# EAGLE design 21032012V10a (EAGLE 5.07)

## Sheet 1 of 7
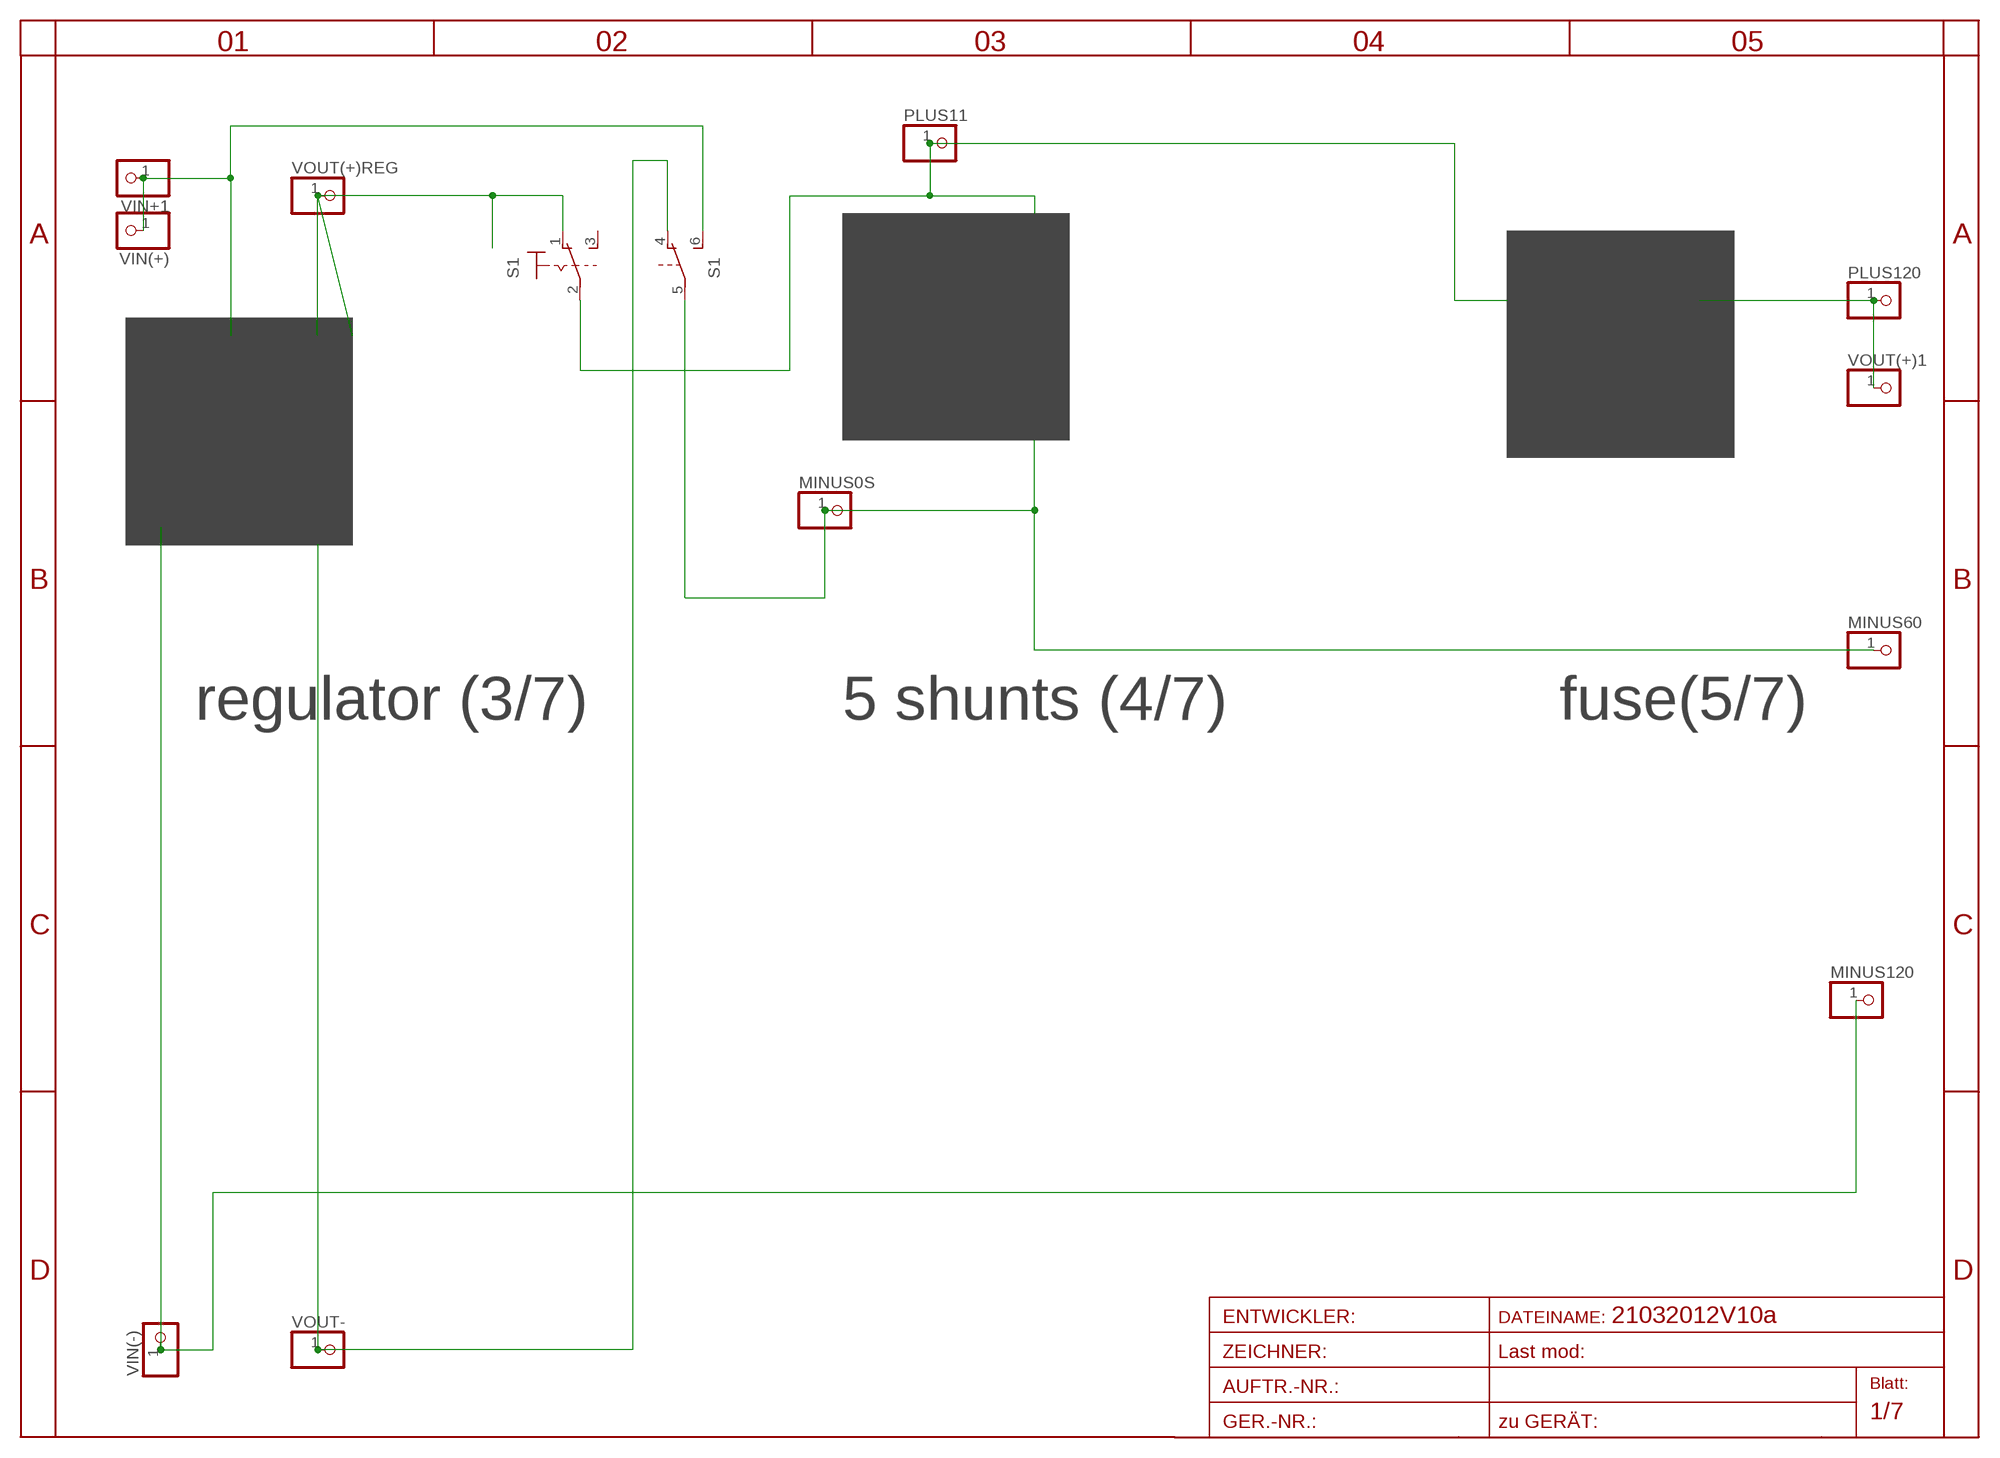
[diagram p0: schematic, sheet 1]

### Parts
MINUS0S  PINHD-1X14.5MM  [1X4MM5]
MINUS60  PINHD-1X14.5MM  [1X4MM5]
MINUS120  PINHD-1X14.5MM  [1X4MM5]
PLUS11  PINHD-1X14.5MM  [1X4MM5]
PLUS120  PINHD-1X14.5MM  [1X4MM5]
S1  320-938320NEW  [320NEW]
VIN(+)  PINHD-1X11MM6  [1X1MM8]
VIN(-)  PINHD-1X1  [1X01]
VIN+1  PINHD-1X1  [1X01]
VOUT(+)1  PINHD-1X11X0.4  [1X01]
VOUT(+)REG  PINHD-1X11X0.4  [1X01]
VOUT-  PINHD-1X11X0.4  [1X01]

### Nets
BATT-: MINUS0S.1 MINUS60.1 S1.5(B:P) ; also sheet 4,5,6,7
IN-: MINUS120.1 VIN(-).1 ; also sheet 3
PLUS11: PLUS11.1 S1.2(1:P) ; also sheet 4
V+OUT: PLUS120.1 VOUT(+)1.1 ; also sheet 5
V-: S1.4(B:O) VOUT-.1 ; also sheet 3
VIN+: S1.6(B:S) VIN(+).1 VIN+1.1 ; also sheet 3
VOUT+REG: S1.1(1:O) VOUT(+)REG.1 ; also sheet 3
Unconnected: S1.3(1:S)

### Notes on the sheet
- regulator (3/7) | 5 shunts (4/7) | fuse(5/7)

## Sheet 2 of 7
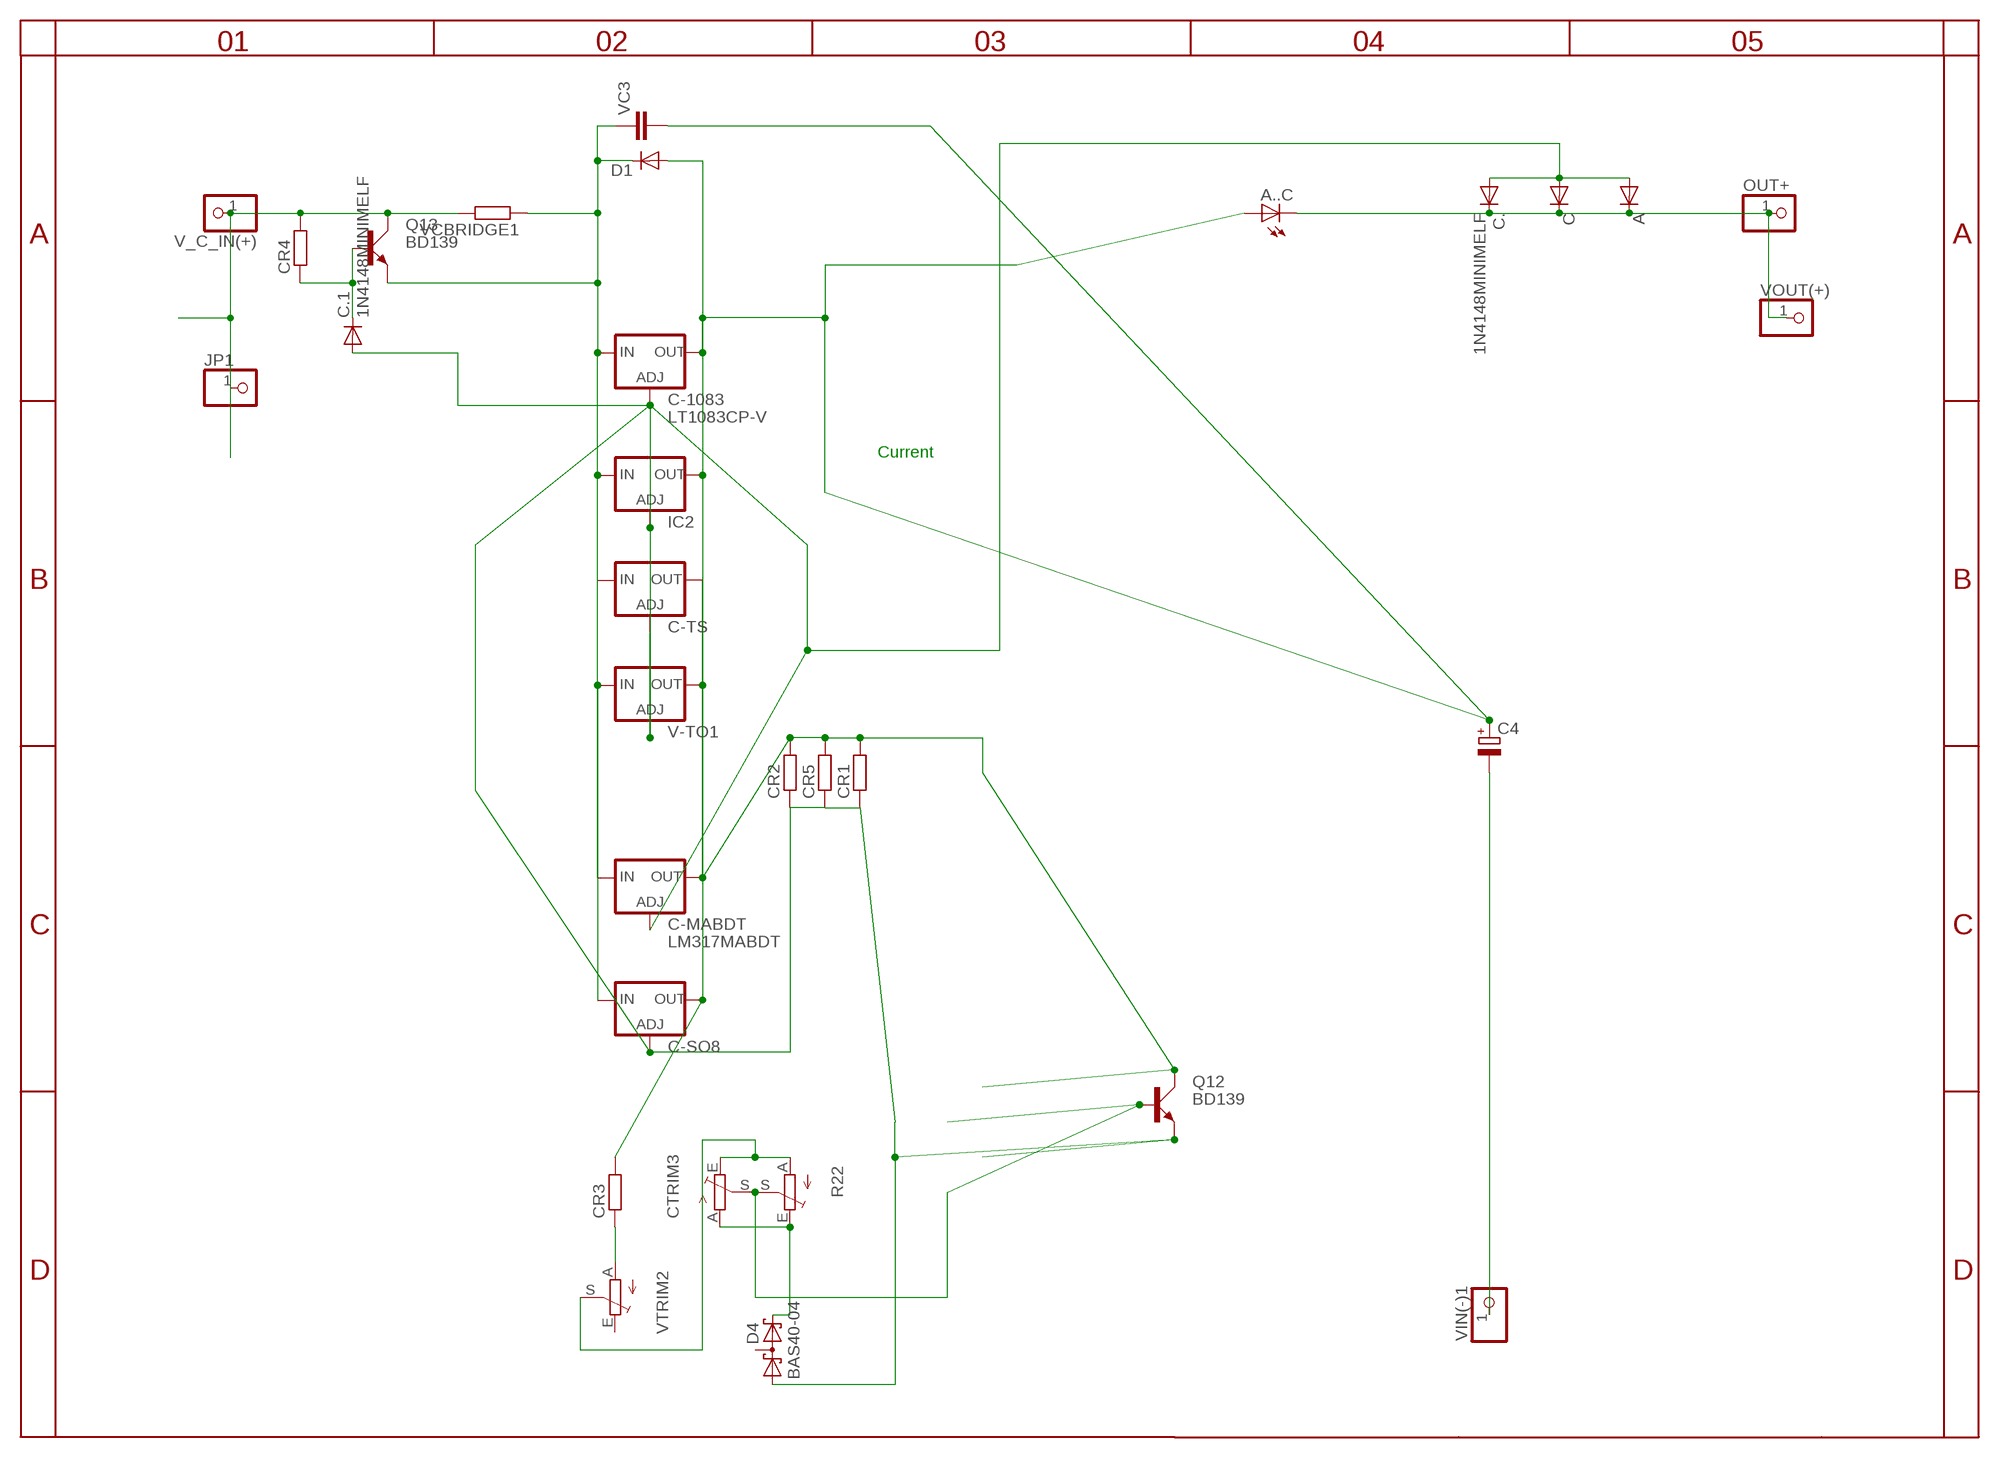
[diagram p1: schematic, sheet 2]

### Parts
A  DIODE-TO220V  [TO220ACS]
A..C  LED3MM  [LED3MM]
C  DIODE-SMB  [SMB]
C4  CPOL-EUE5-6  [E5-6]
C-1083  LT1083CP-V  [TO247S]
C-MABDT  LM317MABDT  [DPACK]
C-SO8  LM317LM-OUTPIN7  [SO08]
C-TS  LM317TS  [317TS]
C.  1N4148MINIMELF  [MINIMELF]
C.1  1N4148MINIMELF  [MINIMELF]
CR1  R-EU_R5025  [R5025]
CR2  R-EU_R1206  [R1206]
CR3  R-EU_R1206  [R1206]
CR4  R-EU_R1206  [R1206]
CR5  R-EU_R1210  [R1210]
CTRIM3  TRIM_EU-EVND_H  [EVND8AA]
D1  DIODE-MINIMELF  [MINIMELF]
D4  BAS40-04  [SOT23]
IC2  LM317LZS  [TO92S]
JP1  PINHD-1X11MM6  [1X1MM8]
OUT+  PINHD-1X1  [1X01]
Q12  BD139  [TO126AV]
Q13  BD139  [TO126AV]
R22  TRIM_EU-RAND160  [RANDL]
V-TO1  LM317-TO3  [TO3-K02]
V_C_IN(+)  PINHD-1X11X0.4  [1X01]
VC3  C-EU050-025X075  [C050-025X075]
VCBRIDGE1  R-EU_R0402  [R0402]
VIN(-)1  PINHD-1X1  [1X01]
VOUT(+)  PINHD-1X11X0.4  [1X01]
VTRIM2  TRIM_EU-EVND_H  [EVND8AA]

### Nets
ADJUST: A.A C-1083.1(ADJ) C-MABDT.1(ADJ) C-SO8.4(ADJ) C-TS.1(ADJ) C.1.A C..A C.A CR1.1 CR2.1 CR5.1 D4.1(A1) IC2.1(ADJ) Q12.E V-TO1.2(ADJ)
B1: CTRIM3.S Q12.B R22.S
INPUT+: C-1083.3(IN) C-MABDT.3(IN) C-SO8.1(IN) C-TS.3(IN) D1.C IC2.3(IN) Q13.E V-TO1.1(IN) VC3.1 VCBRIDGE1.1
MINUS: CTRIM3.A D4.2(C2) R22.E
N$5: CTRIM3.E R22.A VTRIM2.S
N$6: CR3.1 VTRIM2.A
N$9: C4.- VIN(-)1.1
N$84: C.1.C CR4.1 Q13.B
N$85: CR4.2 JP1.1 Q13.C V_C_IN(+).1 VCBRIDGE1.2
OUT1: A..C.A C4.+ C-1083.2(OUT) C-MABDT.4(OUT) C-SO8.7(OUT) C-TS.2(OUT) CR1.2 CR2.2 CR3.2 CR5.2 D1.A IC2.2(OUT) Q12.C V-TO1.3(OUT) VC3.2
OUT+: A..C.K(C) A.C C..C C.C OUT+.1 VOUT(+).1
Unconnected: D4.3(C1A2) VTRIM2.E

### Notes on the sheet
- Current

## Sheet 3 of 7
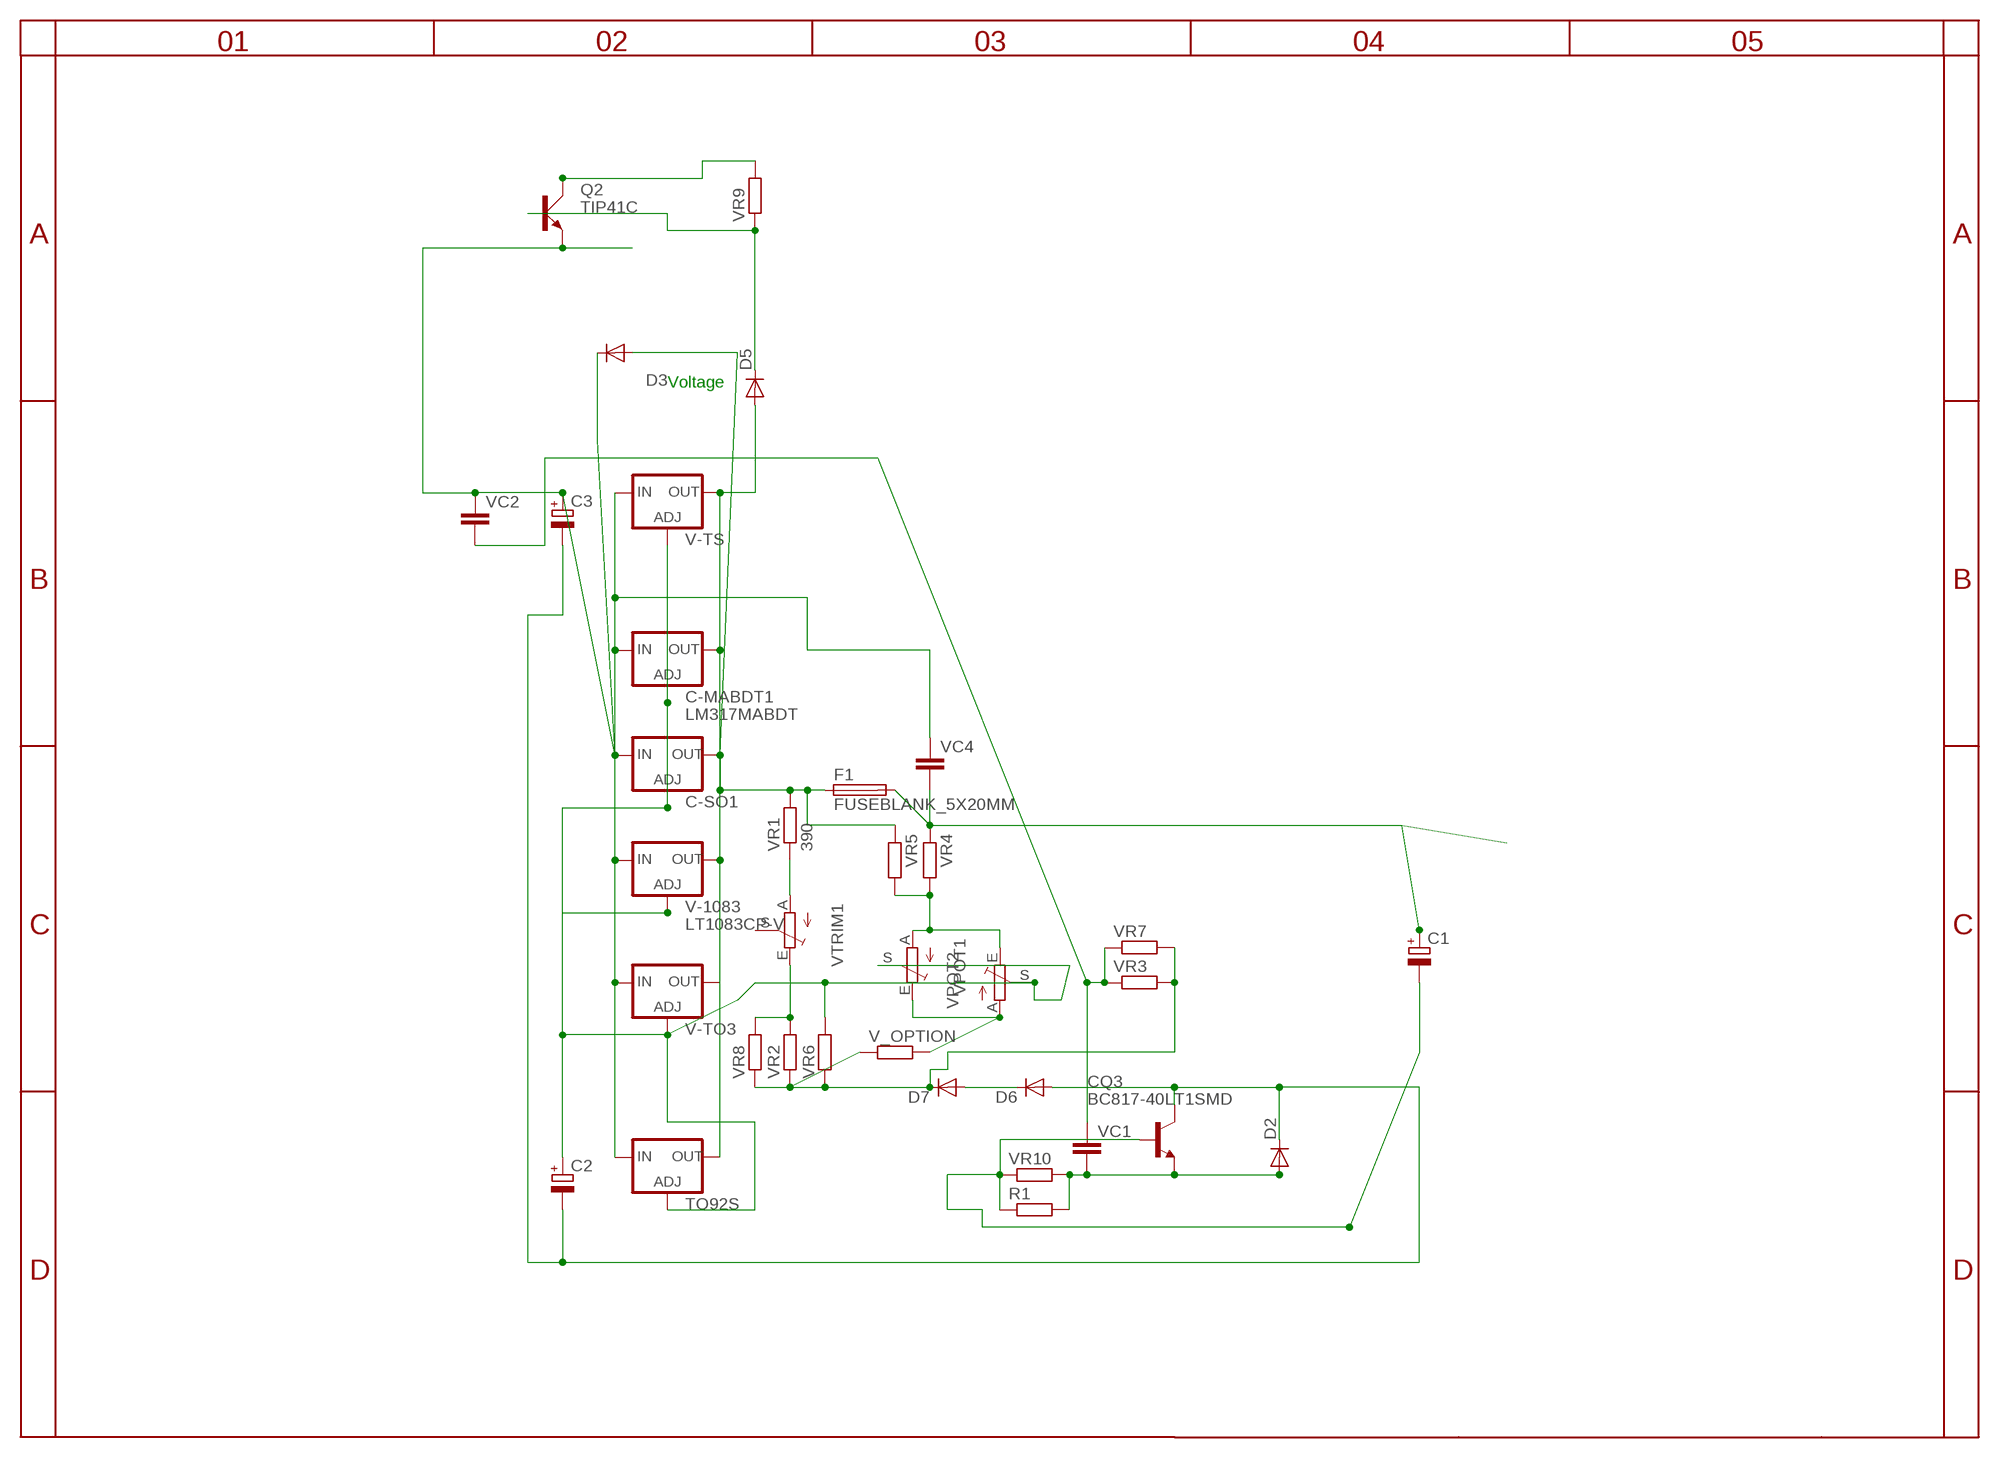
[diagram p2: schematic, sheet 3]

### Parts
C1  CPOL-EUE5-8.5  [E5-8,5]
C2  CPOL-EUE2.5-6  [E2,5-6]
C3  CPOL-EUE2.5-6  [E2,5-6]
C-MABDT1  LM317MABDT  [DPACK]
C-SO1  LM317LM-OUTPIN7  [SO08]
CQ3  BC817-40LT1SMD  [SOT23-BEC]
D2  DIODE-MINIMELF  [MINIMELF]
D3  DIODE-MINIMELF  [MINIMELF]
D5  DIODE-MINIMELF  [MINIMELF]
D6  DIODE-MINIMELF  [MINIMELF]
D7  DIODE-MINIMELF  [MINIMELF]
F1  FUSEBLANK_5X20MM  [FUSE_HOLDER_5X20MM]
Q2  TIP41C  [TO220AV]
R1  R-EU_R2010  [R2010]
TO92S  LM317LZS  [TO92S]
V-1083  LT1083CP-V  [TO247S]
V-TO3  LM317-TO3  [TO3-K02]
V-TS  LM317TS  [317TS]
V_OPTION  R-EU_0204/2V  [0204V]
VC1  C-EU050-025X075  [C050-025X075]
VC2  C-EU050-025X075  [C050-025X075]
VC4  C-EUC1206  [C1206]
VPOT1  TRIM_EU-RAND160  [RANDL]
VPOT2  TRIM_EU-S64W  [S64W]
VR1  390  R-EU_0207/15  [0207/15]
VR2  R-EU_0204/2V  [0204V]
VR3  R-EU_0204/5  [0204/5]
VR4  R-EU_R1206  [R1206]
VR5  R-EU_R1206  [R1206]
VR6  R-EU_R1206  [R1206]
VR7  R-EU_R1206  [R1206]
VR8  R-EU_R1206  [R1206]
VR9  R-EU_R1206  [R1206]
VR10  R-EU_0617/17  [0617/17]
VTRIM1  TRIM_EU-EVND_H  [EVND8AA]

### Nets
ADJ2: C2.+ C-MABDT1.1(ADJ) C-SO1.4(ADJ) TO92S.1(ADJ) V-1083.1(ADJ) V-TO3.2(ADJ) V-TS.1(ADJ) VPOT1.S VPOT2.S VR6.2
IN+1: C3.+ C-MABDT1.3(IN) C-SO1.1(IN) D3.C Q2.E TO92S.3(IN) V-1083.3(IN) V-TO3.1(IN) V-TS.3(IN) VC2.1 VC4.1
IN-: CQ3.E D2.A R1.2 VC1.2 VR10.2 ; also sheet 1
N$1: V_OPTION.2 VPOT1.E VPOT2.A
N$2: VPOT1.A VPOT2.E VR4.2 VR5.2
N$3: VR2.2 VR8.2 VTRIM1.E
N$4: VR1.1 VTRIM1.A
N$7: VC1.1 VC2.2 VR3.1 VR7.1
N$10: D5.C Q2.B VR9.1
N$12: D7.C V_OPTION.1 VR2.1 VR3.2 VR6.1 VR7.2 VR8.1
N$13: D6.C D7.A
OUT2: C-MABDT1.4(OUT) C-SO1.7(OUT) D3.A D5.A F1.1 TO92S.2(OUT) V-1083.2(OUT) V-TO3.3(OUT) V-TS.2(OUT) VR1.2 VR5.1
V-: C1.- CQ3.B R1.1 VR10.1 ; also sheet 1
VIN+: Q2.C VR9.2 ; also sheet 1
VIRT-: C2.- C3.- CQ3.C D2.C D6.A
VOUT+REG: C1.+ F1.2 VC4.2 VR4.1 ; also sheet 1
Unconnected: VTRIM1.S

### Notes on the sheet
- Voltage

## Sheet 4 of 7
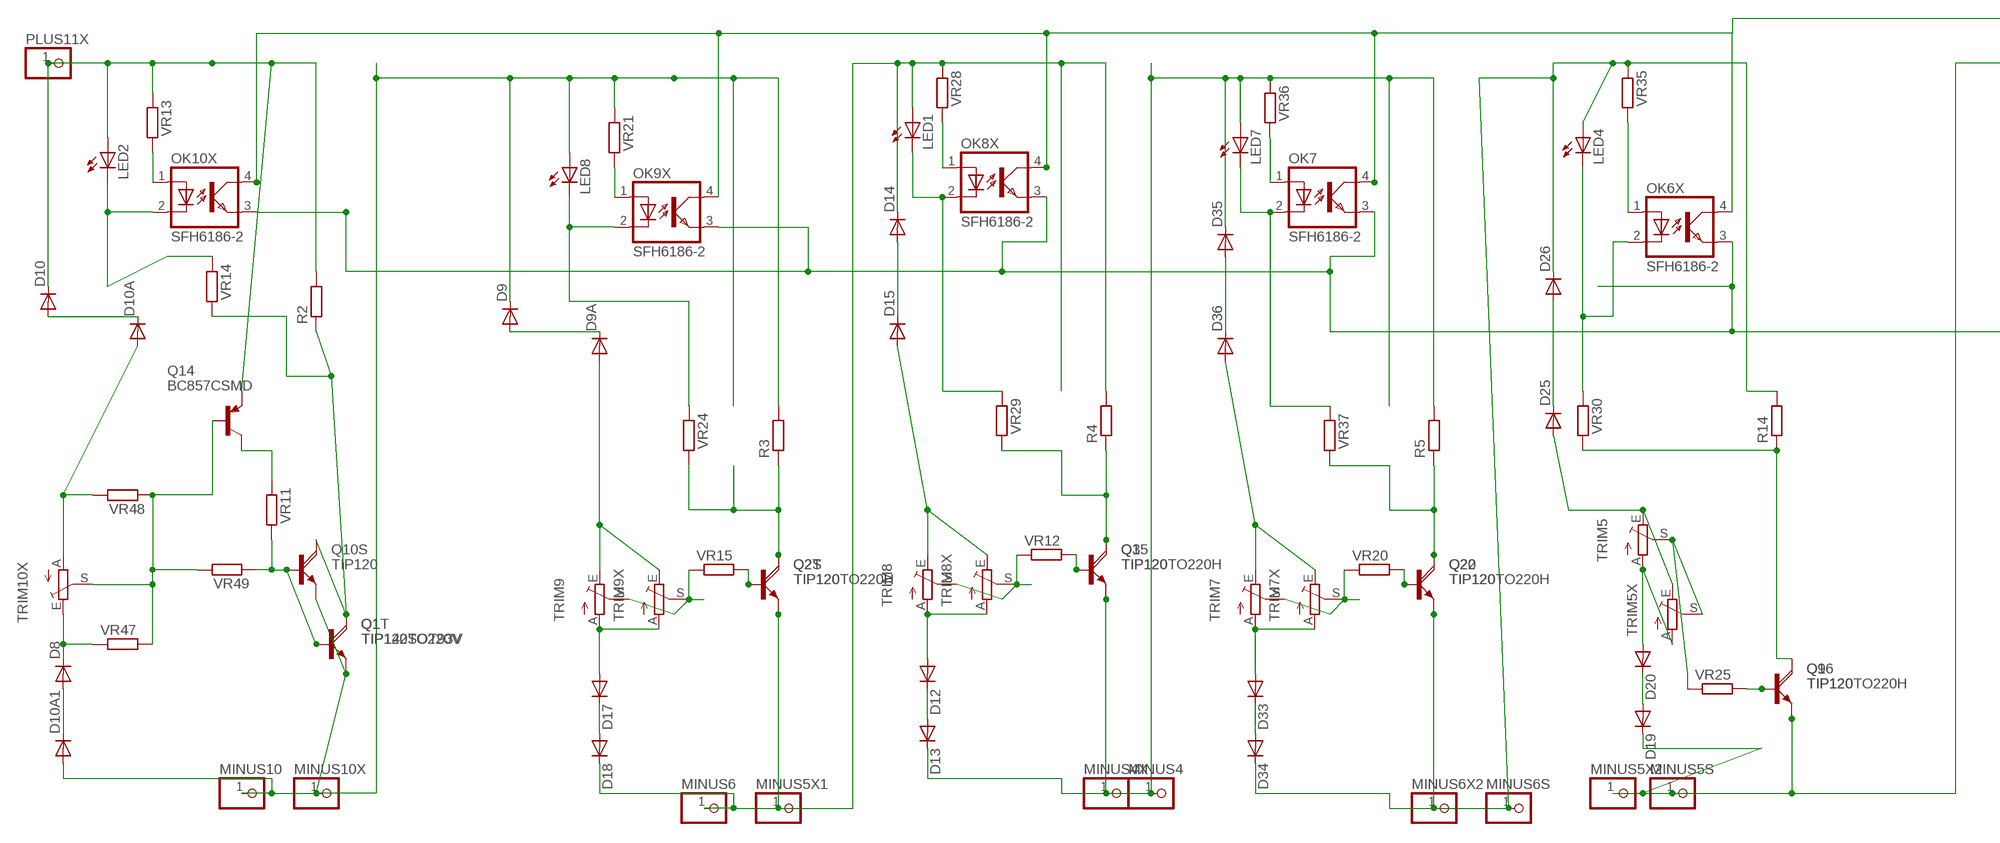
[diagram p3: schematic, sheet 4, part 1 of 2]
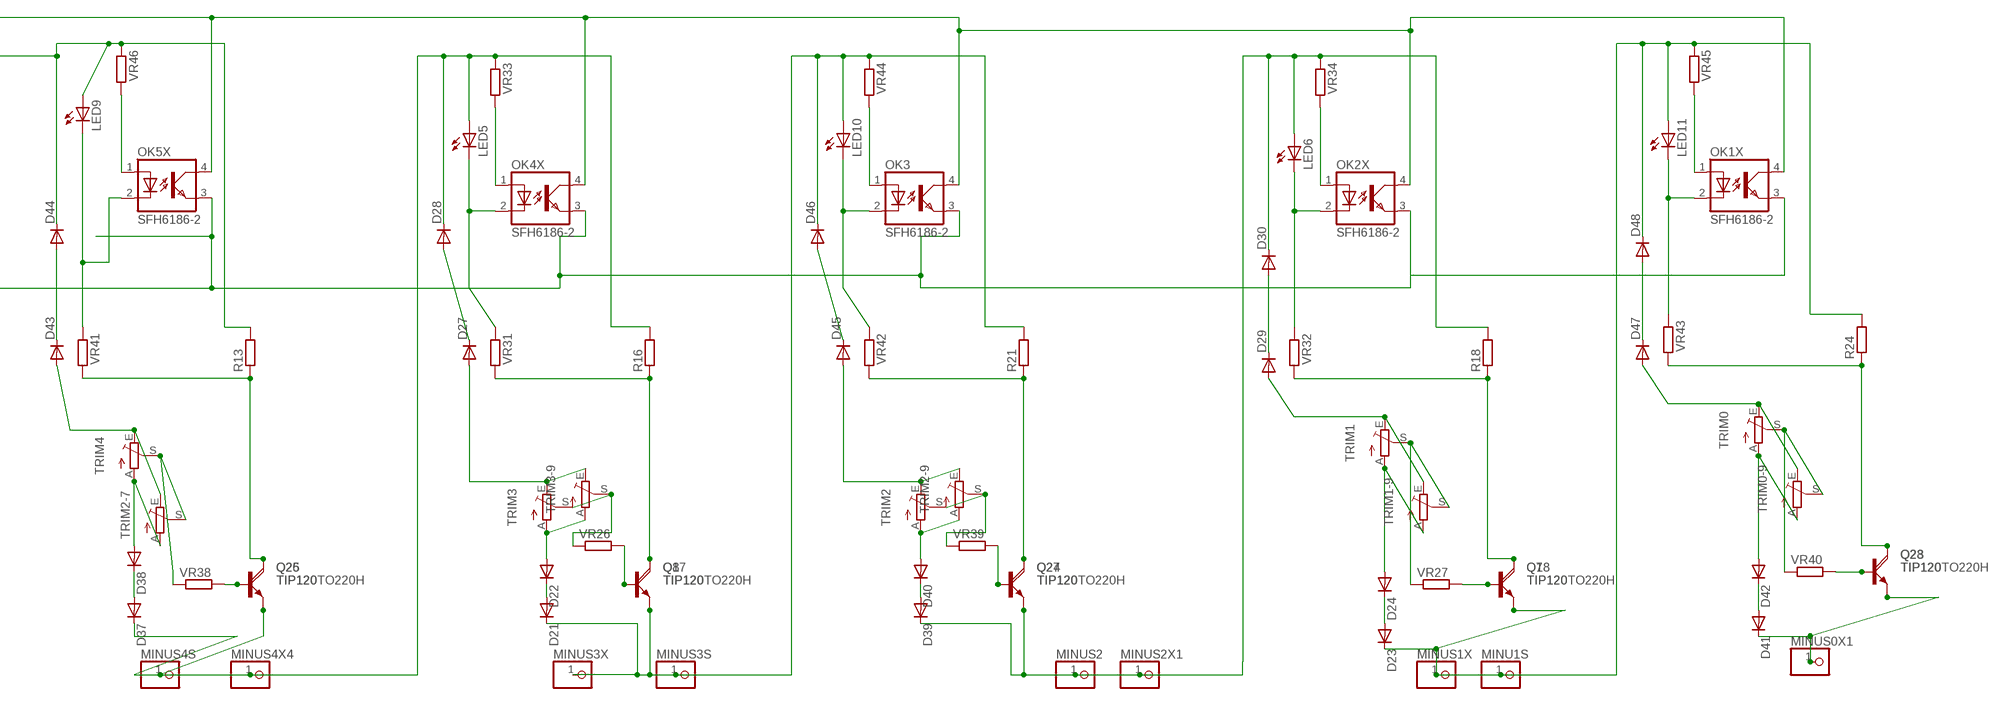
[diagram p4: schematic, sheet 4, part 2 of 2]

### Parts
D8  DIODE-MINIMELF  [MINIMELF]
D9  DIODE-MINIMELF  [MINIMELF]
D9A  DIODE-MINIMELF  [MINIMELF]
D10  DIODE-MINIMELF  [MINIMELF]
D10A  DIODE-MINIMELF  [MINIMELF]
D10A1  DIODE-MINIMELF  [MINIMELF]
D12  DIODE-MINIMELF  [MINIMELF]
D13  DIODE-MINIMELF  [MINIMELF]
D14  DIODE-MINIMELF  [MINIMELF]
D15  DIODE-MINIMELF  [MINIMELF]
D17  DIODE-MINIMELF  [MINIMELF]
D18  DIODE-MINIMELF  [MINIMELF]
D19  DIODE-MINIMELF  [MINIMELF]
D20  DIODE-MINIMELF  [MINIMELF]
D21  DIODE-MINIMELF  [MINIMELF]
D22  DIODE-MINIMELF  [MINIMELF]
D23  DIODE-MINIMELF  [MINIMELF]
D24  DIODE-MINIMELF  [MINIMELF]
D25  DIODE-MINIMELF  [MINIMELF]
D26  DIODE-MINIMELF  [MINIMELF]
D27  DIODE-MINIMELF  [MINIMELF]
D28  DIODE-MINIMELF  [MINIMELF]
D29  DIODE-MINIMELF  [MINIMELF]
D30  DIODE-MINIMELF  [MINIMELF]
D33  DIODE-MINIMELF  [MINIMELF]
D34  DIODE-MINIMELF  [MINIMELF]
D35  DIODE-MINIMELF  [MINIMELF]
D36  DIODE-MINIMELF  [MINIMELF]
D37  DIODE-MINIMELF  [MINIMELF]
D38  DIODE-MINIMELF  [MINIMELF]
D39  DIODE-MINIMELF  [MINIMELF]
D40  DIODE-MINIMELF  [MINIMELF]
D41  DIODE-MINIMELF  [MINIMELF]
D42  DIODE-MINIMELF  [MINIMELF]
D43  DIODE-MINIMELF  [MINIMELF]
D44  DIODE-MINIMELF  [MINIMELF]
D45  DIODE-MINIMELF  [MINIMELF]
D46  DIODE-MINIMELF  [MINIMELF]
D47  DIODE-MINIMELF  [MINIMELF]
D48  DIODE-MINIMELF  [MINIMELF]
LED1  LEDCHIPLED_1206  [CHIPLED_1206]
LED2  LEDCHIPLED_1206  [CHIPLED_1206]
LED4  LEDCHIPLED_1206  [CHIPLED_1206]
LED5  LEDCHIPLED_1206  [CHIPLED_1206]
LED6  LEDCHIPLED_1206  [CHIPLED_1206]
LED7  LEDCHIPLED_1206  [CHIPLED_1206]
LED8  LEDCHIPLED_1206  [CHIPLED_1206]
LED9  LEDCHIPLED_1206  [CHIPLED_1206]
LED10  LEDCHIPLED_1206  [CHIPLED_1206]
LED11  LEDCHIPLED_1206  [CHIPLED_1206]
MINU1S  PINHD-1X14.5MM  [1X4MM5]
MINUS0X1  PINHD-1X11X0.4  [1X01]
MINUS1X  PINHD-1X11X0.4  [1X01]
MINUS2  PINHD-1X14.5MM  [1X4MM5]
MINUS2X1  PINHD-1X11X0.4  [1X01]
MINUS3S  PINHD-1X14.5MM  [1X4MM5]
MINUS3X  PINHD-1X11X0.4  [1X01]
MINUS4  PINHD-1X14.5MM  [1X4MM5]
MINUS4S  PINHD-1X14.5MM  [1X4MM5]
MINUS4X  PINHD-1X11X0.4  [1X01]
MINUS4X4  PINHD-1X11X0.4  [1X01]
MINUS5S  PINHD-1X14.5MM  [1X4MM5]
MINUS5X1  PINHD-1X11X0.4  [1X01]
MINUS5X2  PINHD-1X11X0.4  [1X01]
MINUS6  PINHD-1X14.5MM  [1X4MM5]
MINUS6S  PINHD-1X14.5MM  [1X4MM5]
MINUS6X2  PINHD-1X11X0.4  [1X01]
MINUS10  PINHD-1X14.5MM  [1X4MM5]
MINUS10X  PINHD-1X11X0.4  [1X01]
OK1X  SFH6186-2  [SMD4]
OK2X  SFH6186-2  [SMD4]
OK3  SFH6186-2  [SMD4]
OK4X  SFH6186-2  [SMD4]
OK5X  SFH6186-2  [SMD4]
OK6X  SFH6186-2  [SMD4]
OK7  SFH6186-2  [SMD4]
OK8X  SFH6186-2  [SMD4]
OK9X  SFH6186-2  [SMD4]
OK10X  SFH6186-2  [SMD4]
PLUS11X  PINHD-1X11X0.4  [1X01]
Q1  TIP142SOT93V  [SOT93V]
Q1T  TIP120TO220V  [TO220AV]
Q2S  TIP120  TIP120TO220V  [TO220AV]
Q2T  TIP120TO220H  [TO220AH]
Q3  TIP120  TIP120TO220V  [TO220AV]
Q7  TIP120  TIP120TO220V  [TO220AV]
Q8  TIP120  TIP120TO220V  [TO220AV]
Q9  TIP120  TIP120TO220V  [TO220AV]
Q10S  TIP120  TIP120DPAK  [D-PAK_TO252AA]
Q14  BC857CSMD  [SOT23-BEC]
Q15  TIP120TO220H  [TO220AH]
Q16  TIP120TO220H  [TO220AH]
Q17  TIP120TO220H  [TO220AH]
Q18  TIP120TO220H  [TO220AH]
Q20  TIP120  TIP120TO220V  [TO220AV]
Q22  TIP120TO220H  [TO220AH]
Q23  TIP120  TIP120TO220V  [TO220AV]
Q24  TIP120  TIP120TO220V  [TO220AV]
Q25  TIP120  TIP120TO220V  [TO220AV]
Q26  TIP120TO220H  [TO220AH]
Q27  TIP120TO220H  [TO220AH]
Q28  TIP120TO220H  [TO220AH]
R2  R-EU_CERAM55  [CERAM55]
R3  R-EU_CERAM55  [CERAM55]
R4  R-EU_CERAM55  [CERAM55]
R5  R-EU_CERAM55  [CERAM55]
R13  R-EU_CERAM55  [CERAM55]
R14  R-EU_CERAM55  [CERAM55]
R16  R-EU_CERAM55  [CERAM55]
R18  R-EU_CERAM55  [CERAM55]
R21  R-EU_CERAM55  [CERAM55]
R24  R-EU_CERAM55  [CERAM55]
TRIM0  TRIM_EU-EVND_H  [EVND8AA]
TRIM0-9  TRIM_EU-S64W  [S64W]
TRIM1  TRIM_EU-EVND_H  [EVND8AA]
TRIM1-9  TRIM_EU-S64W  [S64W]
TRIM2  TRIM_EU-EVND_H  [EVND8AA]
TRIM2-7  TRIM_EU-S64W  [S64W]
TRIM2-9  TRIM_EU-S64W  [S64W]
TRIM3  TRIM_EU-EVND_H  [EVND8AA]
TRIM3-9  TRIM_EU-S64W  [S64W]
TRIM4  TRIM_EU-EVND_H  [EVND8AA]
TRIM5  TRIM_EU-EVND_H  [EVND8AA]
TRIM5X  TRIM_EU-S64W  [S64W]
TRIM7  TRIM_EU-EVND_H  [EVND8AA]
TRIM7X  TRIM_EU-S64W  [S64W]
TRIM8  TRIM_EU-EVND_H  [EVND8AA]
TRIM8X  TRIM_EU-S64W  [S64W]
TRIM9  TRIM_EU-EVND_H  [EVND8AA]
TRIM9X  TRIM_EU-S64W  [S64W]
TRIM10X  TRIM_EU-S64W  [S64W]
VR11  R-EU_R1206  [R1206]
VR12  R-EU_R1206  [R1206]
VR13  R-EU_R1206  [R1206]
VR14  R-EU_R1206  [R1206]
VR15  R-EU_R1206  [R1206]
VR20  R-EU_R1206  [R1206]
VR21  R-EU_R1206  [R1206]
VR24  R-EU_R1206  [R1206]
VR25  R-EU_R1206  [R1206]
VR26  R-EU_R1206  [R1206]
VR27  R-EU_R1206  [R1206]
VR28  R-EU_R1206  [R1206]
VR29  R-EU_R1206  [R1206]
VR30  R-EU_R1206  [R1206]
VR31  R-EU_R1206  [R1206]
VR32  R-EU_R1206  [R1206]
VR33  R-EU_R1206  [R1206]
VR34  R-EU_R1206  [R1206]
VR35  R-EU_R1206  [R1206]
VR36  R-EU_R1206  [R1206]
VR37  R-EU_R1206  [R1206]
VR38  R-EU_R1206  [R1206]
VR39  R-EU_R1206  [R1206]
VR40  R-EU_R1206  [R1206]
VR41  R-EU_R1206  [R1206]
VR42  R-EU_R1206  [R1206]
VR43  R-EU_R1206  [R1206]
VR44  R-EU_R1206  [R1206]
VR45  R-EU_R1206  [R1206]
VR46  R-EU_R1206  [R1206]
VR47  R-EU_R0402  [R0402]
VR48  R-EU_R0402  [R0402]
VR49  R-EU_R0402  [R0402]

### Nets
B: Q14.B TRIM10X.S VR47.2 VR48.1 VR49.2
B2: TRIM8.S TRIM8X.S VR12.1
B3: TRIM9.S TRIM9X.S VR15.1
B4: TRIM7.S TRIM7X.S VR20.1
BATT-: D41.C MINUS0X1.1 OK1X.3(EMIT) OK2X.3(EMIT) OK3.3(EMIT) OK4X.3(EMIT) OK5X.3(EMIT) OK6X.3(EMIT) OK7.3(EMIT) OK8X.3(EMIT) OK9X.3(EMIT) OK10X.3(EMIT) Q23.E Q28.E ; also sheet 1,5,6,7
MINUS2: D23.C D48.C LED11.A MINU1S.1 MINUS1X.1 Q7.E Q18.E R24.2 VR45.1
MX4: D28.C D37.C LED5.A MINUS4S.1 MINUS4X4.1 Q25.E Q26.E R16.2 VR33.1
N$8: D13.C D35.C LED7.A MINUS4.1 MINUS4X.1 Q3.E Q15.E R5.2 VR36.1
N$11: LED2.C OK10X.2(C) VR14.1
N$14: D10A.A TRIM10X.A VR48.2
N$15: Q14.C VR11.1
N$16: OK8X.1(A) VR28.2
N$17: D10.A D10A.C
N$20: D9A.A TRIM9.E TRIM9X.E
N$23: OK10X.1(A) VR13.2
N$24: D8.A D10A1.C
N$25: Q1.B Q1T.B Q10S.1(B) VR11.2 VR49.1
N$26: D15.A TRIM8.E TRIM8X.E
N$27: D12.A TRIM8.A TRIM8X.A
N$29: D14.A D15.C
N$30: D17.A TRIM9.A TRIM9X.A
N$31: LED1.C OK8X.2(C) VR29.1
N$32: D12.C D13.A
N$33: Q3.B Q15.B VR12.2
N$45: OK1X.4(COL) OK2X.4(COL) OK3.4(COL) OK4X.4(COL) OK5X.4(COL) OK6X.4(COL) OK7.4(COL) OK8X.4(COL) OK9X.4(COL) OK10X.4(COL) ; also sheet 6
N$50: Q9.B Q16.B VR25.2
N$51: Q8.B Q17.B VR26.2
N$52: Q7.B Q18.B VR27.2
N$54: D20.A TRIM5.A TRIM5X.A
N$55: D25.A TRIM5.E TRIM5X.E
N$56: D9.A D9A.C
N$57: TRIM5.S TRIM5X.S VR25.1
N$58: Q8.C Q17.C R16.1 VR31.2
N$59: D19.C D44.C LED9.A MINUS5S.1 MINUS5X2.1 Q9.E Q16.E R13.2 VR46.1
N$60: D30.C D39.C LED6.A MINUS2.1 MINUS2X1.1 Q24.E Q27.E R18.2 VR34.1
N$61: Q7.C Q18.C R18.1 VR32.2
N$62: D22.A TRIM3-9.A TRIM3.A
N$63: D27.A TRIM3-9.E TRIM3.E
N$64: TRIM3-9.S TRIM3.S VR26.1
N$65: D24.A TRIM1-9.A TRIM1.A
N$66: D29.A TRIM1-9.E TRIM1.E
N$67: TRIM1-9.S TRIM1.S VR27.1
N$68: D23.A D24.C
N$70: D21.A D22.C
N$71: D25.C D26.A
N$72: D19.A D20.C
N$73: D27.C D28.A
N$74: D29.C D30.A
N$77: LED4.C OK6X.2(C) VR30.1
N$78: LED5.C OK4X.2(C) VR31.1
N$79: LED6.C OK2X.2(C) VR32.1
N$80: OK6X.1(A) VR35.2
N$81: OK4X.1(A) VR33.2
N$82: OK2X.1(A) VR34.2
N$86: D17.C D18.A
N$87: Q2S.B Q2T.B VR15.2
N$88: D36.A TRIM7.E TRIM7X.E
N$89: D33.A TRIM7.A TRIM7X.A
N$90: Q24.C Q27.C R21.1 VR42.2
N$91: D35.A D36.C
N$92: D33.C D34.A
N$93: Q20.B Q22.B VR20.2
N$94: LED8.C OK9X.2(C) VR24.1
N$95: OK9X.1(A) VR21.2
N$97: Q23.C Q28.C R24.1 VR43.2
N$98: D26.C D34.C LED4.A MINUS6S.1 MINUS6X2.1 Q20.E Q22.E R14.2 VR35.1
N$99: OK7.1(A) VR36.2
N$100: LED7.C OK7.2(C) VR37.1
N$101: D14.C D18.C LED1.A MINUS5X1.1 MINUS6.1 Q2S.E Q2T.E R4.2 VR28.1
N$102: Q25.B Q26.B VR38.2
N$103: Q24.B Q27.B VR39.2
N$104: Q23.B Q28.B VR40.2
N$105: D38.A TRIM2-7.A TRIM4.A
N$106: D43.A TRIM2-7.E TRIM4.E
N$107: TRIM2-7.S TRIM4.S VR38.1
N$108: D40.A TRIM2-9.A TRIM2.A
N$109: D45.A TRIM2-9.E TRIM2.E
N$110: TRIM2-9.S TRIM2.S VR39.1
N$111: D42.A TRIM0-9.A TRIM0.A
N$112: D47.A TRIM0-9.E TRIM0.E
N$113: TRIM0-9.S TRIM0.S VR40.1
N$114: D41.A D42.C
N$115: D39.A D40.C
N$116: D37.A D38.C
N$117: D21.C D46.C LED10.A MINUS3S.1 MINUS3X.1 Q8.E Q17.E R21.2 VR44.1
N$118: D43.C D44.A
N$119: D45.C D46.A
N$120: D47.C D48.A
N$121: LED9.C OK5X.2(C) VR41.1
N$122: LED10.C OK3.2(C) VR42.1
N$123: LED11.C OK1X.2(C) VR43.1
N$124: OK5X.1(A) VR46.2
N$125: OK3.1(A) VR44.2
N$126: OK1X.1(A) VR45.2
N$128: D8.C TRIM10X.E VR47.1
PLUS10: D9.C D10A1.A LED8.A MINUS10.1 MINUS10X.1 Q1.E Q1T.E Q10S.3(E) R3.2 VR21.1
PLUS11: D10.C LED2.A PLUS11X.1 Q14.E R2.2 VR13.1 ; also sheet 1
Q1C: Q1.C Q1T.C Q10S.4(C) R2.1 VR14.2
Q1C1: Q2S.C Q2T.C R3.1 VR24.2
Q2C: Q3.C Q15.C R4.1 VR29.2
Q2C1: Q20.C Q22.C R5.1 VR37.2
Q3C: Q9.C Q16.C R14.1 VR30.2
Q3C1: Q25.C Q26.C R13.1 VR41.2

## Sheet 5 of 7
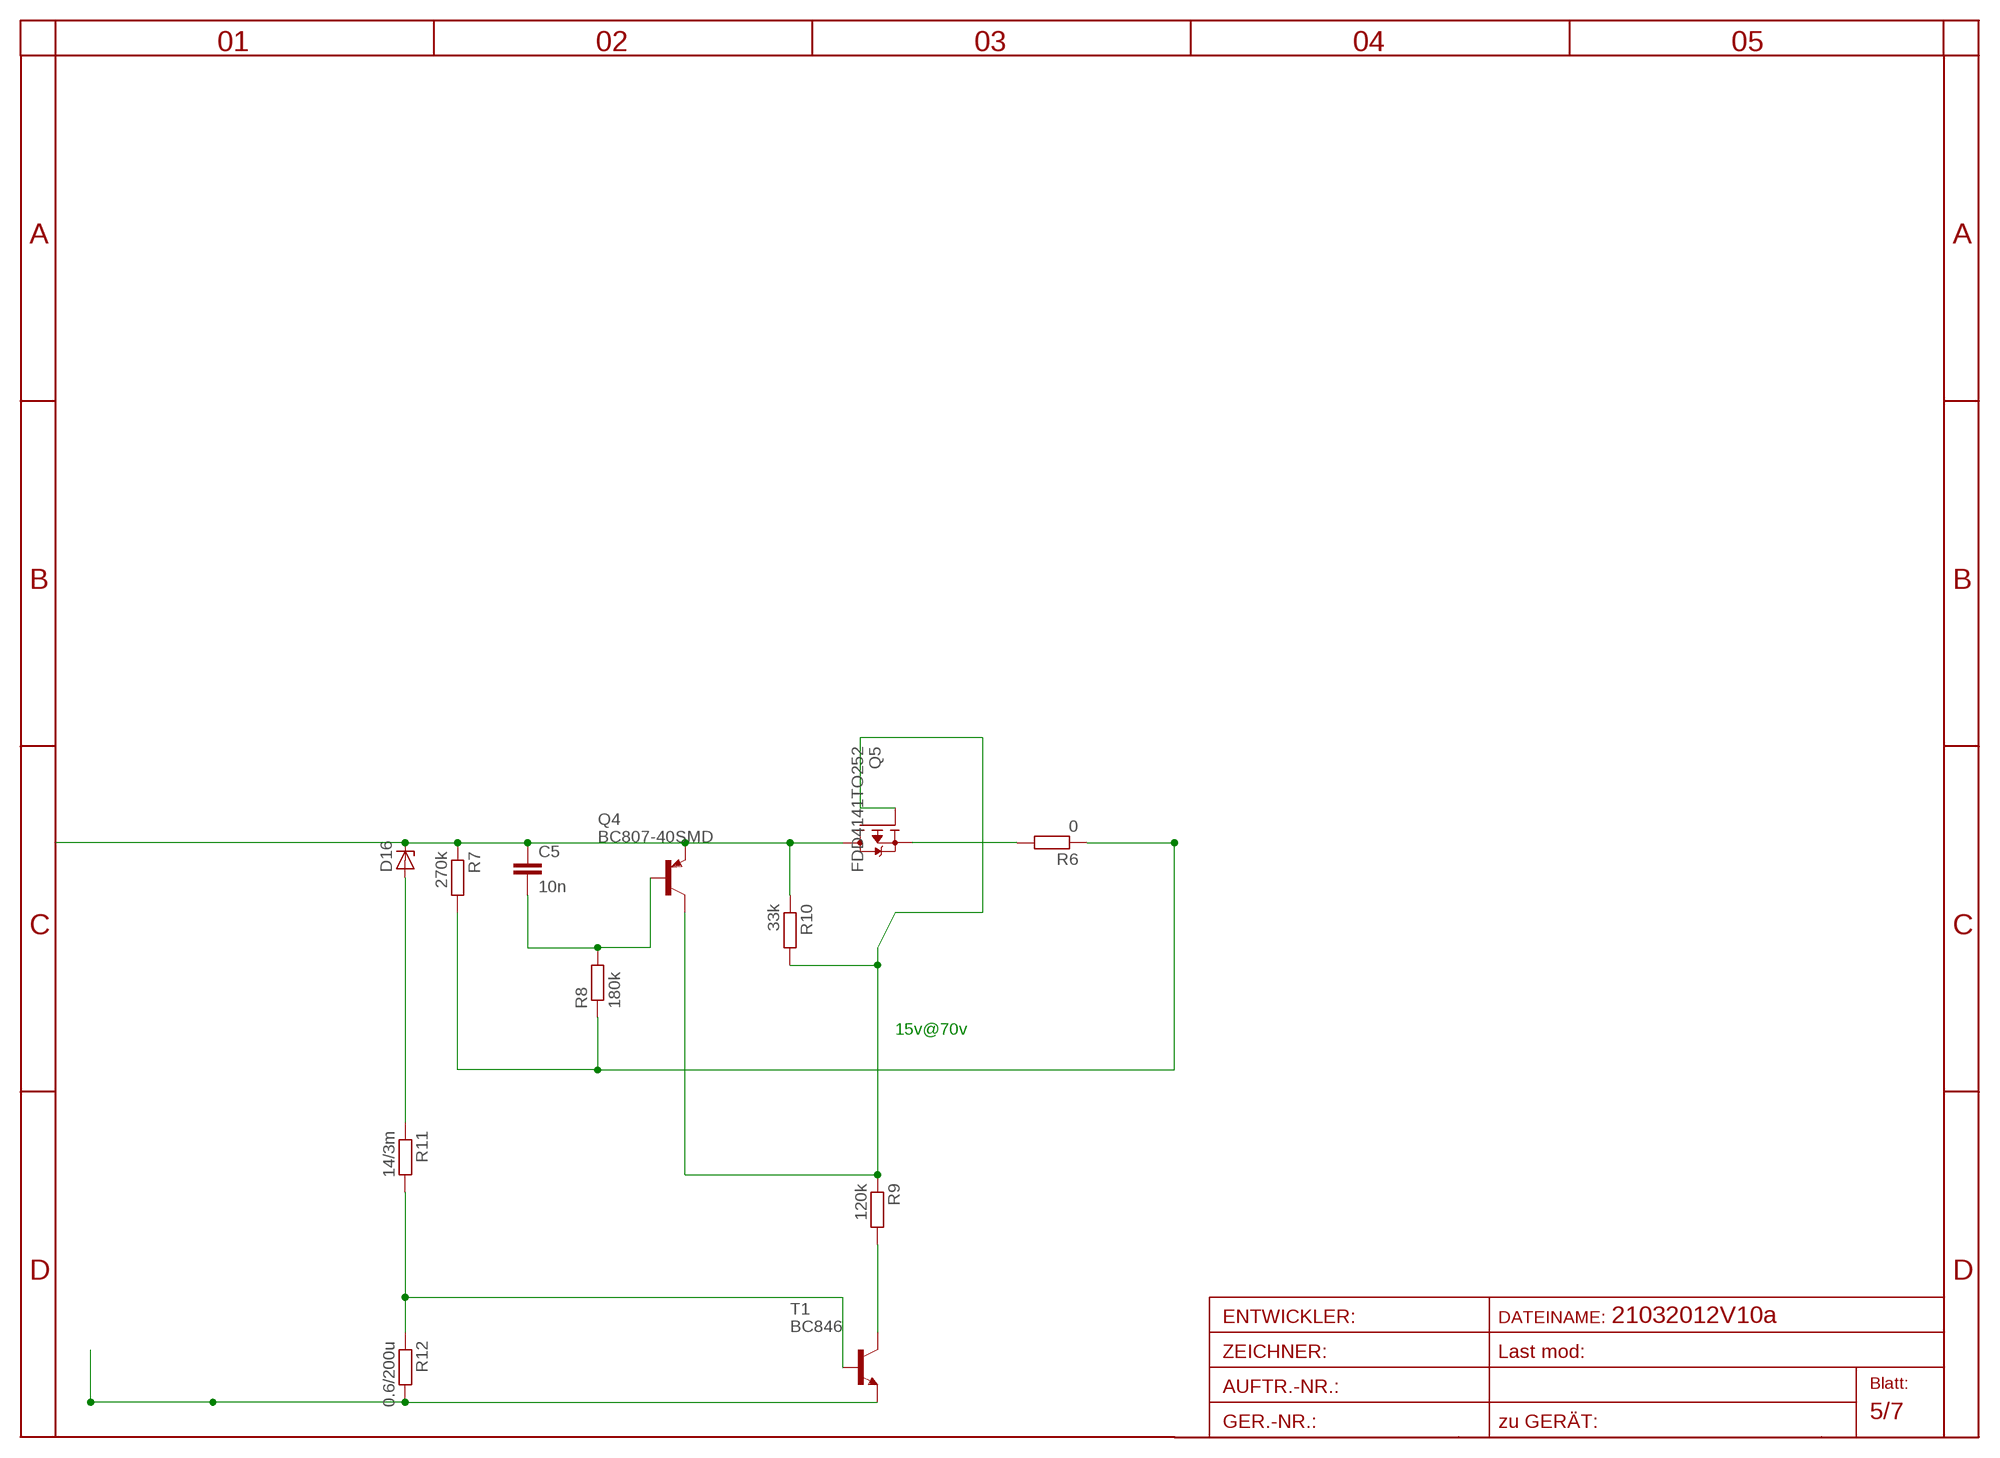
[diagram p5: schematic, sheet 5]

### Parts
C5  10n  C-EUC1206  [C1206]
D16  ZENER-DIODESOD80C  [SOD80C]
Q4  BC807-40SMD  [SOT23-BEC]
Q5  FDD4141TO252  [TO252]
R6  0  R-EU_0204/7  [0204/7]
R7  270k  R-EU_R1206  [R1206]
R8  180k  R-EU_R1206  [R1206]
R9  120k  R-EU_R1206  [R1206]
R10  33k  R-EU_R1206  [R1206]
R11  14/3m  R-EU_R1206  [R1206]
R12  0.6/200u  R-EU_R1206  [R1206]
T1  BC846  [SOT23]

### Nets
B-Q1: C5.2 Q4.B R8.2
BATT-: R12.2 T1.2(E) ; also sheet 1,4,6,7
D: Q5.3(S) R6.2
GATE: Q4.C Q5.1(G) R9.1 R10.2
N$18: R9.2 T1.3(C)
N$19: D16.A R11.1
N$21: R11.2 R12.1 T1.1(B)
PLUS5: C5.1 D16.C Q4.E Q5.2(D) R7.1 R10.1 ; also sheet 6,7
V+OUT: R6.1 R7.2 R8.1 ; also sheet 1

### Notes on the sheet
- 15v@70v

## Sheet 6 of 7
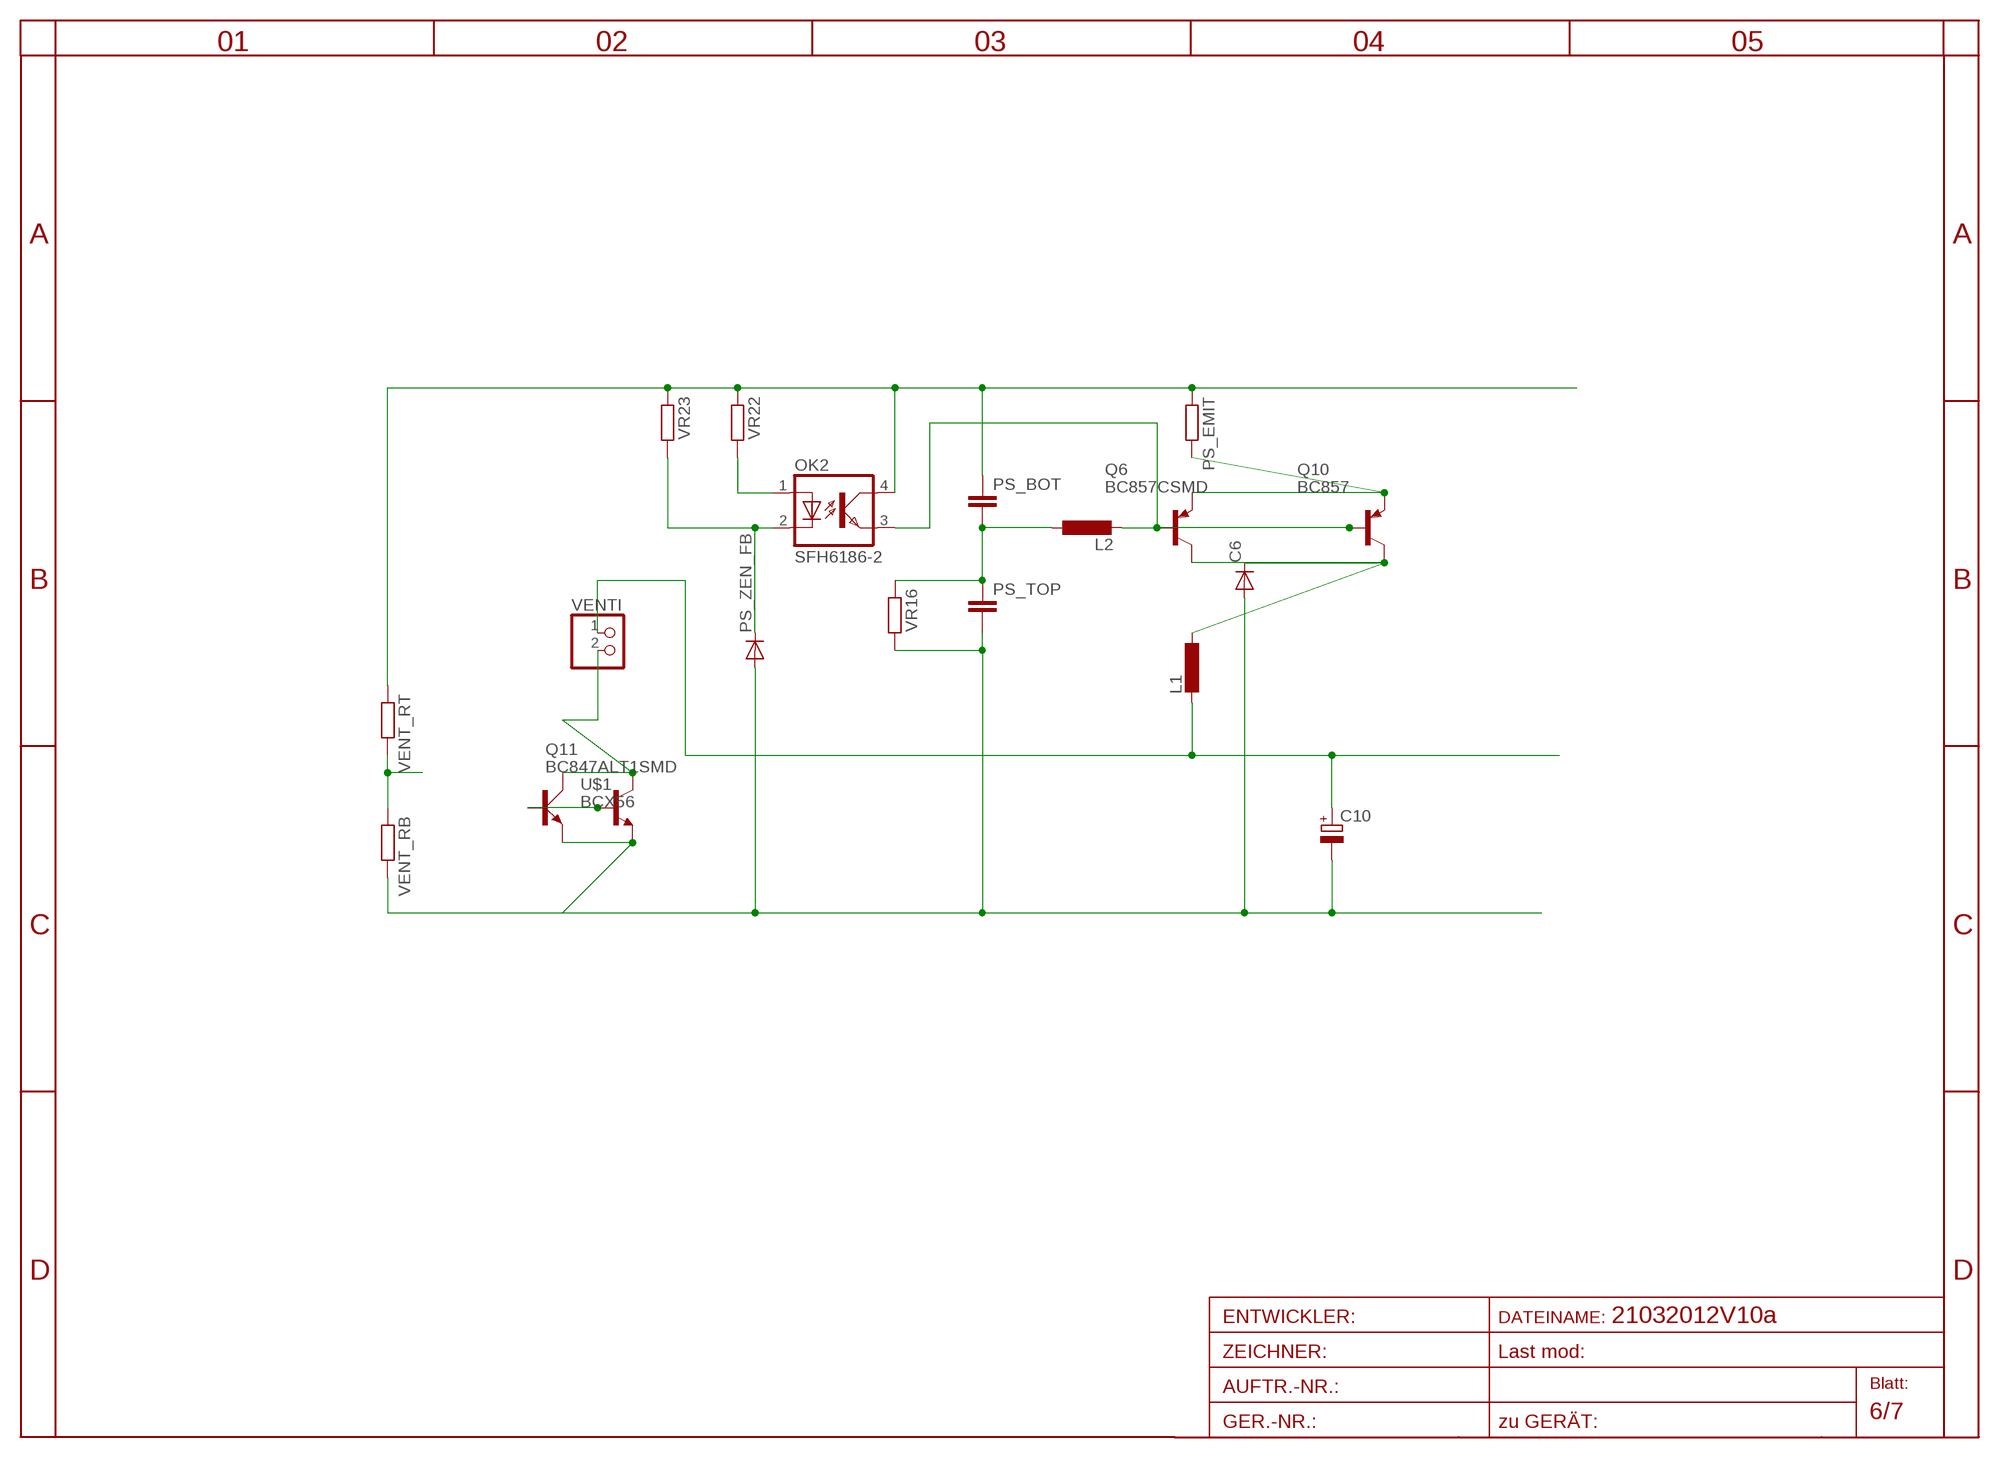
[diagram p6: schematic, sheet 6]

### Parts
C6  DIODE-SMB  [SMB]
C10  CPOL-EUE2.5-6  [E2,5-6]
L1  L-EUL5650M  [L5650M]
L2  L-EUL5650M  [L5650M]
OK2  SFH6186-2  [SMD4]
PS_BOT  C-EUC1206  [C1206]
PS_EMIT  R-EU_R1210  [R1210]
PS_TOP  C-EUC1206  [C1206]
PS_ZEN_FB  DIODE-MINIMELF  [MINIMELF]
Q6  BC857CSMD  [SOT23-BEC]
Q10  BC857  [SOT223]
Q11  BC847ALT1SMD  [SOT23]
U$1  BCX56  [SOT223]
VENT_RB  R-EU_R1206  [R1206]
VENT_RT  R-EU_R1206  [R1206]
VENTI  PINHD-1X2  [1X02]
VR16  R-EU_R1206  [R1206]
VR22  R-EU_R1206  [R1206]
VR23  R-EU_R1206  [R1206]

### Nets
BATT-: C6.A C10.- PS_TOP.2 PS_ZEN_FB.A Q11.2(E) U$1.3(E) VENT_RB.2 VR16.2 ; also sheet 1,4,5,7
N$22: C10.+ L1.2 VENTI.1 ; also sheet 7
N$38: PS_EMIT.2 Q6.E Q10.3(E)
N$39: L2.2 OK2.3(EMIT) Q6.B Q10.1(B)
N$40: C6.C L1.1 Q6.C Q10.2(C)
N$41: OK2.2(C) PS_ZEN_FB.C VR23.2
N$42: OK2.1(A) VR22.2
N$43: L2.1 PS_BOT.2 PS_TOP.1 VR16.1
N$44: VENT_RB.1 VENT_RT.2
N$45: Q11.1(B) U$1.1(B) ; also sheet 4
N$53: Q11.3(C) U$1.2(C) VENTI.2
PLUS5: OK2.4(COL) PS_BOT.1 PS_EMIT.1 VENT_RT.1 VR22.1 VR23.1 ; also sheet 5,7

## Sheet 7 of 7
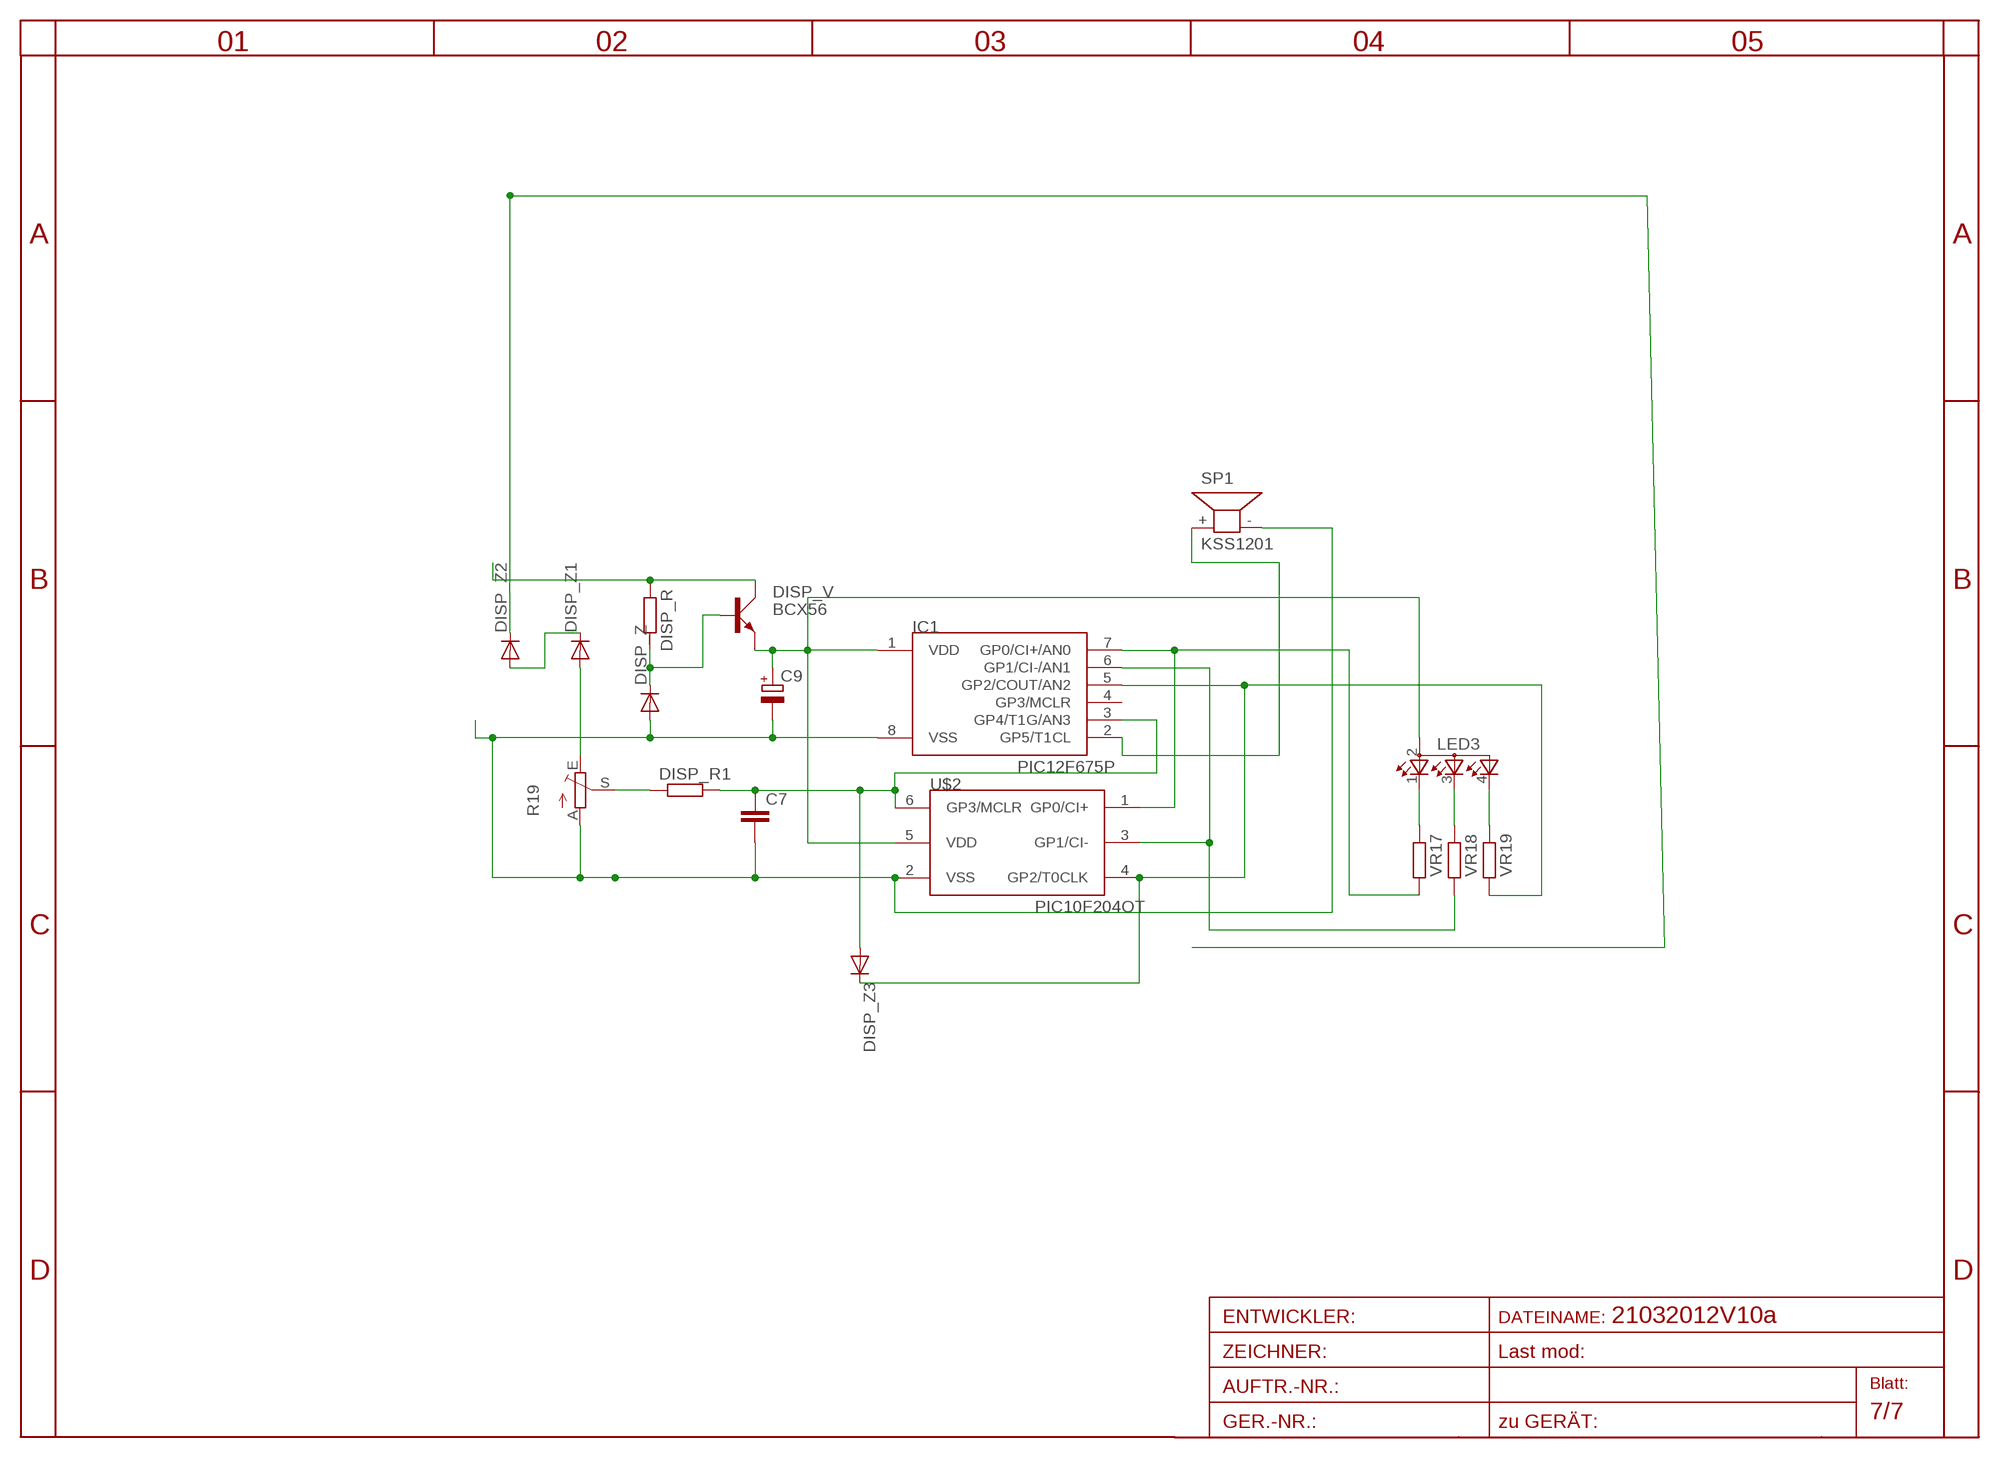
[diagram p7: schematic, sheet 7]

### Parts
C7  C-EUC1206  [C1206]
C9  CPOL-EUE5-6  [E5-6]
DISP_R  R-EU_R1206  [R1206]
DISP_R1  R-EU_R1206  [R1206]
DISP_V  BCX56  [SOT223]
DISP_Z  DIODE-MINIMELF  [MINIMELF]
DISP_Z1  DIODE-MINIMELF  [MINIMELF]
DISP_Z2  DIODE-MINIMELF  [MINIMELF]
DISP_Z3  DIODE-MINIMELF  [MINIMELF]
IC1  PIC12F675P  [DIL8]
LED3  TOPLED-3  [P-LCC-4-3]
R19  TRIM_EU-CA6V  [CA6V]
SP1  KSS1201  [KSS1201]
U$2  PIC10F204OT  [SOT23-6]
VR17  R-EU_R1206  [R1206]
VR18  R-EU_R1206  [R1206]
VR19  R-EU_R1206  [R1206]

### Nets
BATT-: C7.2 C9.- DISP_Z.A IC1.8(VSS) R19.A SP1.- U$2.2(VSS) ; also sheet 1,4,5,6
N$22: DISP_R.1 DISP_V.2(C) ; also sheet 6
N$34: C9.+ DISP_V.3(E) IC1.1(VDD) LED3.2(A2) U$2.5(VDD)
N$35: IC1.7(GP0/CI+/AN0) U$2.1(GP0/CI+) VR17.2
N$36: IC1.6(GP1/CI-/AN1) U$2.3(GP1/CI-) VR18.2
N$37: DISP_Z3.C IC1.5(GP2/COUT/AN2) U$2.4(GP2/T0CLK) VR19.2
N$46: DISP_R.2 DISP_V.1(B) DISP_Z.C
N$47: LED3.1(CRED) VR17.1
N$48: LED3.3(CBLUE) VR18.1
N$49: LED3.4(CGREEN) VR19.1
N$69: DISP_Z1.A R19.E
N$75: C7.1 DISP_R1.2 DISP_Z3.A IC1.3(GP4/T1G/AN3) U$2.6(GP3/MCLR)
N$76: DISP_R1.1 R19.S
N$83: DISP_Z1.C DISP_Z2.A
N$96: IC1.2(GP5/T1CL) SP1.+
PLUS5: DISP_Z2.C ; also sheet 5,6
Unconnected: IC1.4(GP3/MCLR)

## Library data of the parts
A C C6 D1-D3 D5-D9 D9A D10 D10A D10A1 D12-D15 D17-D30 D33-D48 DISP_Z DISP_Z1-DISP_Z3 PS_ZEN_FB = diode:DIODE-: DIODE
A..C LED1 LED2 LED4-LED11 = led:LED: LED
C1-C4 C9 C10 = rcl:CPOL-EU: POLARIZED CAPACITOR, European symbol
C5 = rcl-2:C-EU: CAPACITOR, European symbol
C7 PS_BOT PS_TOP VC1-VC4 = rcl:C-EU: CAPACITOR, European symbol
C-1083 V-1083 = linear-technology-2:LT1083*: 7.5A Low Dropout Positive Adjustable Regulators
C-MABDT C-MABDT1 = v-reg:LM317?*: 500 mA Adjustable Output Positive Voltage Regulator Source: http://www.onsemi.co.jp .. LM317M-D.PDF
C-SO1 C-SO8 IC2 TO92S = v-reg-3:LM317L: Adjustable Voltage Regulator, 1.2V to 37V, 100mA
C-TS V-TS = v-reg:LM317TS: VOLTAGE REGULATOR
C. C.1 = diode-1:1N4148: DIODE
CQ3 = transistor-npn:BC817*: NPN Transistor
CR1-CR5 DISP_R DISP_R1 PS_EMIT R6-R12 V_OPTION VCBRIDGE1 VENT_RB VENT_RT VR1-VR49 = rcl-2:R-EU_: RESISTOR, European symbol
CTRIM3 R22 TRIM0 TRIM0-9 TRIM1 TRIM1-9 TRIM2 TRIM2-7 TRIM2-9 TRIM3 TRIM3-9 TRIM4 TRIM5 TRIM5X TRIM7 TRIM7X TRIM8 TRIM8X TRIM9 TRIM9X TRIM10X VPOT1 VPOT2 VTRIM1 VTRIM2 = pot:TRIM_EU-: POTENTIOMETER
D4 = diode:BAS40-04: Silicon Schottky Diodes General-purpose diode for high-speed switching
D16 = diode-1:ZENER-DIODE: Z-Diode
DISP_V U$1 = transistor-power:BCX56
F1 = fuse:FUSE: Fuse
IC1 = microchip-5:PIC12F6*: uPC nW 1k Program Flash memory 2x Timer Comparator 10b A/D converter/ 4xIN
JP1 MINU1S MINUS0S MINUS0X1 MINUS1X MINUS2 MINUS2X1 MINUS3S MINUS3X MINUS4 MINUS4S MINUS4X MINUS4X4 MINUS5S MINUS5X1 MINUS5X2 MINUS6 MINUS6S MINUS6X2 MINUS10 MINUS10X MINUS60 MINUS120 PLUS11 PLUS11X PLUS120 V_C_IN(+) VIN(+) VOUT(+) VOUT(+)1 VOUT(+)REG VOUT- = pinhead:PINHD-1X1: PIN HEADER
L1 L2 = rcl:L-EU: INDUCTOR, European symbol
LED3 = led:TOPLED-3: OSRAM - Hyper Multi TOPLED® (RGB) LB E673, LV E673, LT E673 - Power TOPLED® Enhanced optical Power LED (HOP2000) LS E67B, LA E67B, LO E67B, LY E67B - Hyper Multi TOPLED® Enhanced optical Power LED (HOP2000 / ATON®) LATB T66B - Hyper Multi TOPLED® Hyper-Bright LED LATB T686 Source: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
OK1X OK2 OK2X OK3 OK4X OK5X OK6X OK7 OK8X OK9X OK10X = optocoupler:SFH618?*: Optocoupler, Phototransistor Output, Low Input Current Source: http://www.vishay.com/docs/83673/sfh618.pdf
OUT+ VIN(-) VIN(-)1 VIN+1 = pinhead(2):PINHD-1X1: PIN HEADER
Q1 = transistor-power:TIP142: NPN DARLINGTON TRANSISTOR
Q1T Q2S Q2T Q3 Q7-Q9 Q10S Q15-Q18 Q20 Q22-Q28 = transistor-power:TIP120: NPN DARLINGTON TRANSISTOR
Q2 = transistor-power:TIP41C: NPN TRANSISTOR
Q4 = transistor-pnp:BC807*: PNP Transistror
Q5 = transistor-fet:FDD4141: P-Channel PowerTrench® MOSFET Source: FDD4141.pdf
Q6 Q10 Q14 = transistor-pnp:BC857*: PNP Transistror
Q11 = transistor-npn:BC847*: NPN Transistor
Q12 Q13 = transistor-power:BD139: NPN TRANSISTOR
R1-R5 R13 R14 R16 R18 R21 R24 = rcl:R-EU_: RESISTOR, European symbol
R19 = pot-7:TRIM_EU-: POTENTIOMETER
S1 = switch:320-938: TOGGLE SWITCH distributor RS Components
SP1 = buzzer:KSS1201: SPEAKER
T1 = transistor:BC846: NPN TRANSISTOR
U$2 = microchip-5:PIC10F2*: uPC nW 0,25/0,5k Program Flash memory Comparator
V-TO1 V-TO3 = v-reg:LM317-TO3: VOLTAGE REGULATOR
VENTI = pinhead(2):PINHD-1X2: PIN HEADER

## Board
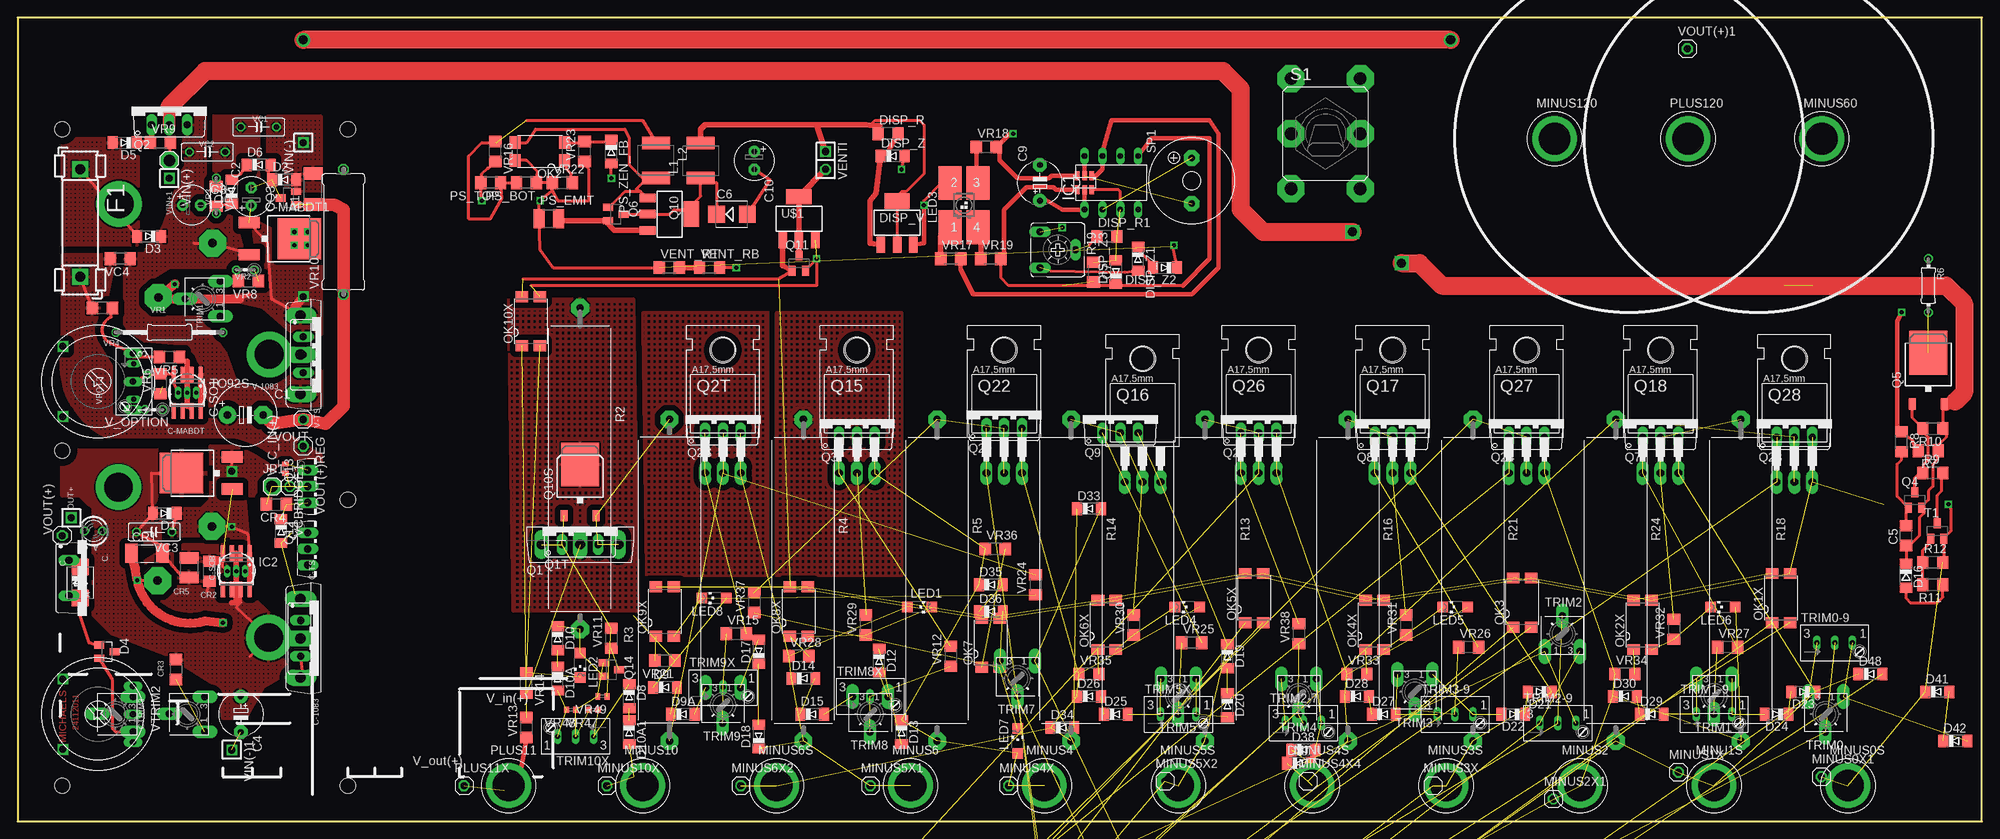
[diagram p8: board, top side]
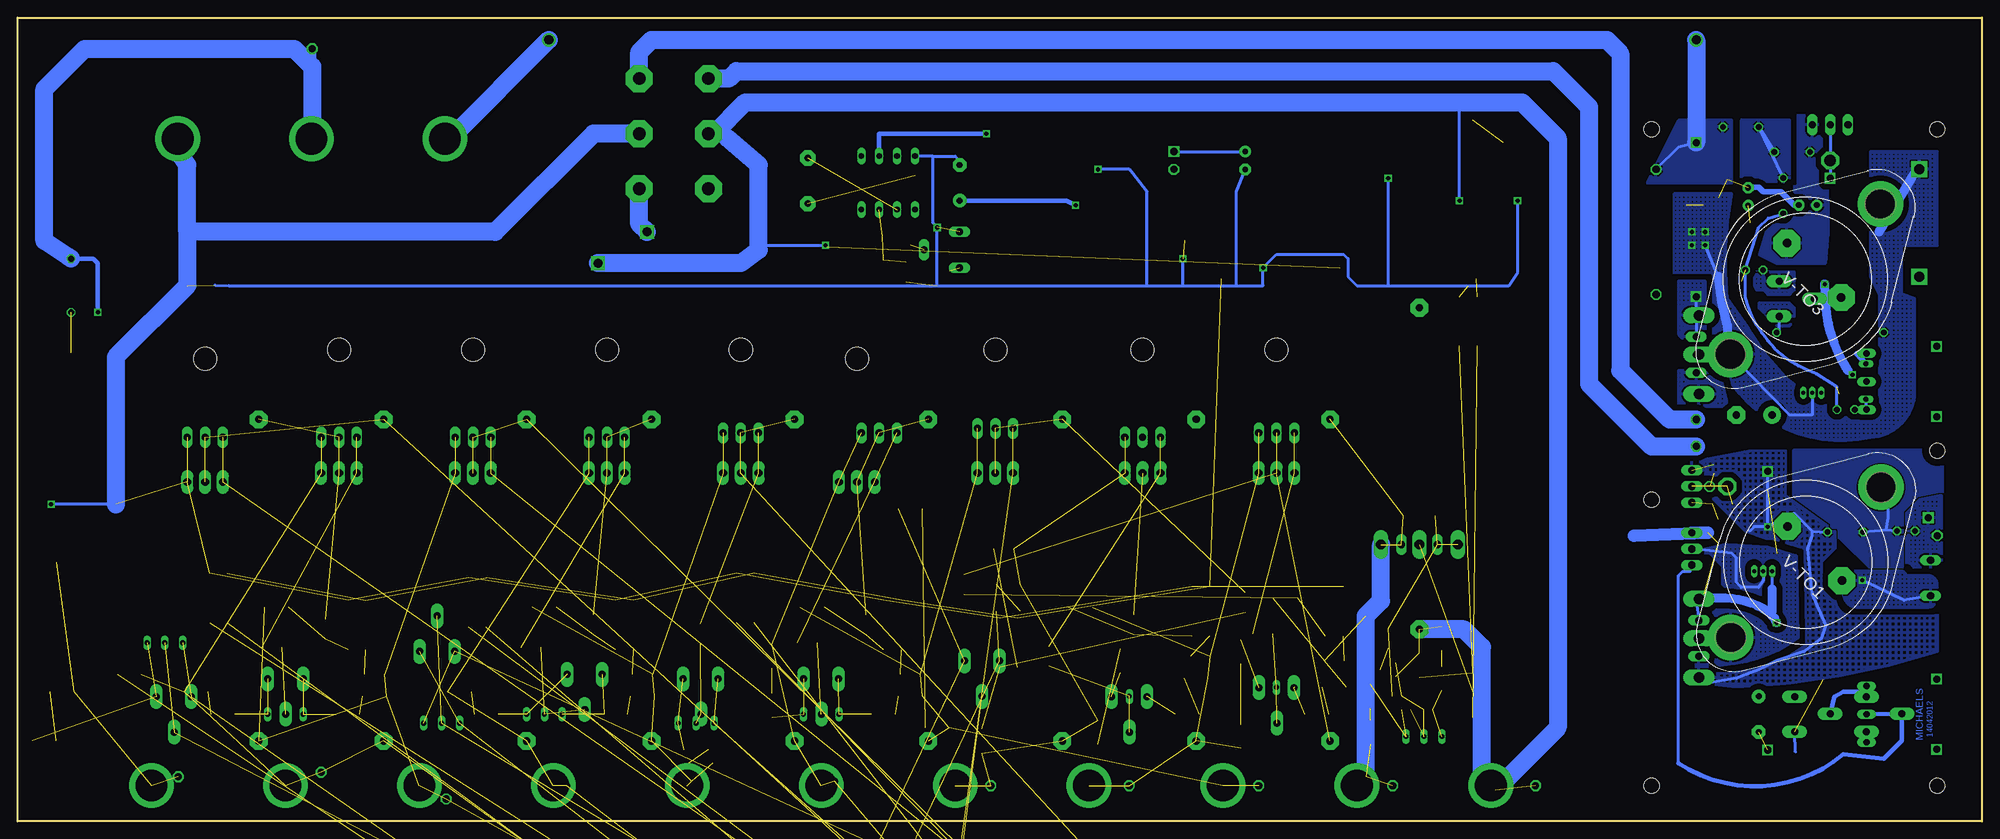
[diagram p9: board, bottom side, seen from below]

Size 279.4 x 114.3 mm. Coordinates in mm from the lower left corner, seen from the top.
Outline: 279.4,0 279.4,114.3 0,114.3 0,0 279.4,0
Copper layers (1*16): Top 0.035mm / dielectric 1.5mm / Bottom 0.035mm
Design rules "default *": minimum track width 10mil, minimum drill 24mil, track to track 8mil, track to pad 8mil, pad to pad 8mil, via to via 8mil, smd to smd 8mil, copper to edge 40mil, drill to drill 8mil, minimum pad ring 1mil, minimum via ring 8mil, stop-mask expansion 4mil, vias tented up to drill 0mil, thermal gap 10mil
Holes 2.2 mm at 6.35,5.08 46.99,45.72 6.35,52.7 46.99,5.08 6.35,98.42 46.99,98.42

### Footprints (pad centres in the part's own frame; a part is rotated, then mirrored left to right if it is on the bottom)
TO220ACS = drill 1.016 long: A 2.54,-2.54; C -2.54,-2.54
LED3MM = drill 0.813 octagon: A -1.27,0; K 1.27,0
SMB = smd 2.4 x 2.4: A 2.2,0; C -2.2,0
E5-8,5 = drill 1.016 pad 2.54 round: + -2.54,0 | drill 1.016 pad 2.54 octagon: - 2.54,0
E2,5-6 = drill 0.813 pad 1.6 round: + -1.27,0 | drill 0.813 pad 1.6 octagon: - 1.27,0
E5-6 = drill 0.813 pad 1.905 round: + -2.54,0 | drill 0.813 pad 1.905 octagon: - 2.54,0
C1206 = smd 1.6 x 1.8: 1 -1.4,0; 2 1.4,0
TO247S = drill 1.499 long: 1 -5.588,-2.921; 2 0,-2.921; 3 5.588,-2.921
DPACK = smd 1.6 x 3: 1 -2.28,-4.8; 3 2.28,-4.8 | smd 5.8 x 6.2: 4 0,2.38
SO08 = smd 0.6 x 2.2: 1 -1.905,-2.6; 2 -0.635,-2.6; 3 0.635,-2.6; 4 1.905,-2.6; 5 1.905,2.6; 6 0.635,2.6; 7 -0.635,2.6; 8 -1.905,2.6
317TS = drill 1.016 long: 1 -2.54,-2.54; 2 0,-2.54; 3 2.54,-2.54
MINIMELF = smd 1.4 x 1.8: A 1.7,0; C -1.7,0
SOT23-BEC = smd 1 x 1.4: B -0.95,-1.1; C 0,1.1; E 0.95,-1.1
R5025 = smd 1.8 x 2.7: 1 -2.2,0; 2 2.2,0
R1206 = smd 1.6 x 1.803: 1 -1.422,0; 2 1.422,0
R1210 = smd 1.6 x 2.7: 1 -1.4,0; 2 1.4,0
EVND8AA = drill 1 pad 1.778 long: A -2.5,-2.5; E 2.5,-2.5; S 0.04,2.54
SOT23 = smd 1 x 1.4: 1 -0.95,-1.1; 2 0.95,-1.1; 3 0,1.1
SOD80C = smd 1.4 x 1.8: A 1.7,0; C -1.7,0
SOT223 = smd 1.219 x 2.235: 1 -2.311,-3.099; 2 0,-3.099; 3 2.311,-3.099 | smd 3.6 x 2.2: 4 0,3.099
FUSE_HOLDER_5X20MM = drill 1.422 pad 2.286 square: 1 0,0; 2 15.24,0
DIL8 = drill 0.813 long: 1 -3.81,-3.81; 2 -1.27,-3.81; 3 1.27,-3.81; 4 3.81,-3.81; 5 3.81,3.81; 6 1.27,3.81; 7 -1.27,3.81; 8 -3.81,3.81
TO92S = drill 0.6 pad 0.813 long: 1 -1.27,0; 2 0,0; 3 1.27,0
1X1MM8 = drill 1.6 pad 2.54 octagon: 1 0,0
L5650M = smd 1.8 x 4: 1 -2.5,0; 2 2.5,0
CHIPLED_1206 = smd 1.5 x 1.5: A 0,-1.75; C 0,1.75
P-LCC-4-3 = smd 3.3 x 4.8: 1 -2,-3.15; 2 -2,3.15; 3 2,3.15; 4 2,-3.15
1X4MM5 = drill 4.5 pad 6.35 round: 1 0,0
1X01 = drill 1.016 octagon: 1 0,0
SMD4 = smd 1.78 x 1.55: 1 -1.27,-3.5; 2 1.27,-3.5; 3 1.27,3.5; 4 -1.27,3.5
1X01' = drill 1.016 square: 1 0,0
SOT93V = drill 1.397 long: B -5.461,-2.54; C 0,-2.54; E 5.461,-2.54
TO220AV = drill 1.016 long: B -2.54,-2.54; C 0,-2.54; E 2.54,-2.54
TO220AH = drill 1.118 long: B -2.54,-6.35; C 0,-6.35; E 2.54,-6.35 | hole 3.302: 0,11.176
TO252 = smd 1 x 1.6: 1 -2.28,-4.8; 2 2.28,-4.8 | smd 5.4 x 6.2: 3 0,2.5
D-PAK_TO252AA = smd 1 x 1.6: 1 -2.28,-4.8; 3 2.28,-4.8 | smd 5.4 x 6.2: 4 0,2.5
TO126AV = drill 1.016 long: B 2.286,-1.27; C 0,-1.27; E -2.286,-1.27
R2010 = smd 1.8 x 2.7: 1 -2.2,0; 2 2.2,0
CERAM55 = drill 1 pad 2.54 octagon: 1 -22.86,0; 2 22.86,0
0204/7 = drill 0.813 octagon: 1 -3.81,0; 2 3.81,0
CA6V = drill 1.016 long: A -2.54,-2.54; E 2.54,-2.54; S 0,2.54
RANDL = drill 0.9 long: A -4,5; E 4,5; S 0,5 | drill 1 square: P$1 -5,-5; P$2 5,-5
320NEW = drill 1.8 pad 3.81 octagon: 1 -4.928,7.823; 2 -4.928,0; 3 -4.928,-7.823; 4 4.928,7.823; 5 4.928,0; 6 4.928,-7.823
KSS1201 = drill 0.914 pad 2.159 octagon: + 3.251,0; - -3.251,0
S64W = drill 0.7 long: A 2.54,1.27; E -2.54,1.27; S 0,1.27
SOT23-6 = smd 0.635 x 1.27: 1 -1.016,-1.016; 2 0,-1.016; 3 1.016,-1.016; 4 1.016,1.016; 5 0,1.016; 6 -1.016,1.016
TO3-K02 = drill 1.194 pad 3.81 octagon: 1 -1.778,-5.461; 2 -1.778,5.461 | drill 4.115 pad 6.477 round: 3 15.113,0; 3@ -15.113,0
0204V = drill 0.813 octagon: 1 -1.27,0; 2 1.27,0
C050-025X075 = drill 0.813 octagon: 1 -2.54,0; 2 2.54,0
R0402 = smd 0.7 x 0.9: 1 -0.65,0; 2 0.65,0
1X02 = drill 1.016 square: 1 -1.27,0 | drill 1.016 octagon: 2 1.27,0
0207/15 = drill 0.813 octagon: 1 -7.62,0; 2 7.62,0
0204/5 = drill 0.813 octagon: 1 -2.54,0; 2 2.54,0
0617/17 = drill 1.016 octagon: 1 -8.89,0; 2 8.89,0

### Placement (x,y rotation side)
A  9.84,34.61 270 top
A..C  10.79,41.27 180 top
C  8.89,33.97 270 top
C1  32.38,57.78 0 top
C2  33.24,88.84 90 top
C3  24.77,87.63 0 top
C4  31.75,15.24 270 top
C5  268.61,40.64 90 top
C6  101.6,86.36 0 top
C7  153.03,78.11 270 top
C9  145.41,90.81 90 top
C10  104.78,93.98 270 top
C-1083  43.18,26.04 270 top
C-MABDT  25.72,49.53 90 top
C-MABDT1  37.72,82.87 270 top
C-SO1  24.13,60.96 180 top
C-SO8  31.11,35.56 180 top
C-TS  42.8,26.04 270 top
C.  8.57,33.97 270 top
C.1  37.47,41.27 270 top
CQ3  38.54,88.65 90 top
CR1  18.41,38.1 0 top
CR2  27.3,35.56 270 top
CR3  22.54,21.59 90 top
CR4  36.83,45.09 180 top
CR5  24.38,36.07 270 top
CTRIM3  13.92,15.24 90 top
D1  20.95,43.81 180 top
D2  37.91,91.25 0 top
D3  18.73,83.19 180 top
D4  12.7,24.13 270 top
D5  15.24,96.52 180 top
D6  34.29,93.34 0 top
D7  30.48,89.53 90 top
D8  87,17.78 270 top
D9  92.08,19.05 0 top
D9A  94.61,15.24 0 top
D10  76.83,26.04 270 top
D10A  76.83,20.32 270 top
D10A1  87,12.7 270 top
D12  122.56,22.86 270 top
D13  125.73,12.7 270 top
D14  111.76,20.32 0 top
D15  113.03,15.24 0 top
D16  268.61,34.92 270 top
D17  105.41,24.13 90 top
D18  105.41,12.06 90 top
D19  172.09,23.5 270 top
D20  172.09,16.51 270 top
D21  216.53,18.41 180 top
D22  212.72,15.24 180 top
D23  254,18.41 180 top
D24  250.19,15.24 180 top
D25  156.21,15.24 0 top
D26  152.4,17.78 0 top
D27  194.31,15.24 0 top
D28  190.5,17.78 0 top
D29  232.41,15.24 0 top
D30  228.6,17.78 0 top
D33  152.4,44.45 0 top
D34  148.59,13.34 0 top
D35  138.43,33.66 0 top
D36  138.43,29.84 0 top
D37  182.25,8.26 0 top
D38  182.88,10.16 0 top
D39  not placed on the board
D40  not placed on the board
D41  273.05,18.41 0 top
D42  275.59,11.43 0 top
D43  not placed on the board
D44  not placed on the board
D45  not placed on the board
D46  not placed on the board
D47  not placed on the board
D48  263.52,20.95 0 top
DISP_R  123.83,97.79 0 top
DISP_R1  154.94,83.19 0 top
DISP_V  125.09,85.09 0 top
DISP_Z  124.46,94.61 0 top
DISP_Z1  159.38,80.01 270 top
DISP_Z2  163.19,78.74 180 top
DISP_Z3  156.21,78.11 90 top
F1  8.89,92.71 270 top
IC1  155.57,90.81 0 top
IC2  31.11,35.56 0 top
JP1  36.2,47.62 0 top
L1  97.16,93.98 90 top
L2  90.81,93.98 270 top
LED1  128.27,30.48 270 top
LED2  80.01,22.23 180 top
LED3  134.62,87.63 0 top
LED4  166.37,30.48 90 top
LED5  204.47,30.48 90 top
LED6  242.57,30.48 90 top
LED7  142.24,11.43 0 top
LED8  99.06,31.75 90 top
LED9  not placed on the board
LED10  not placed on the board
LED11  not placed on the board
MINU1S  241.3,5.08 0 top
MINUS0S  260.35,5.08 0 top
MINUS0X1  256.54,6.35 0 top
MINUS1X  236.22,6.99 0 top
MINUS2  222.25,5.08 0 top
MINUS2X1  218.44,3.17 0 top
MINUS3S  203.2,5.08 0 top
MINUS3X  201.29,5.08 0 top
MINUS4  146.05,5.08 0 top
MINUS4S  184.15,5.08 0 top
MINUS4X  140.97,5.08 0 top
MINUS4X4  183.51,5.71 0 top
MINUS5S  165.1,5.08 0 top
MINUS5X1  121.28,5.08 0 top
MINUS5X2  163.19,5.71 0 top
MINUS6  127,5.08 0 top
MINUS6S  107.95,5.08 0 top
MINUS6X2  102.87,5.08 0 top
MINUS10  88.9,5.08 0 top
MINUS10X  83.82,5.08 0 top
MINUS60  256.62,97.08 0 top
MINUS120  218.62,97.08 0 top
OK1X  250.82,31.75 0 top
OK2  74.3,95.25 90 top
OK2X  231.14,27.94 0 top
OK3  214,31.11 0 top
OK4X  193.04,27.94 0 top
OK5X  175.9,31.75 0 top
OK6X  154.94,27.94 0 top
OK7  138.43,25.4 0 top
OK8X  111.12,29.84 0 top
OK9X  92.08,29.84 0 top
OK10X  73.03,71.12 0 top
OUT+  [1X01']  7.62,43.18 0 top
PLUS11  69.85,5.08 0 top
PLUS11X  63.5,5.08 0 top
PLUS120  237.62,97.08 0 top
PS_BOT  72.39,90.81 180 top
PS_EMIT  75.56,85.72 0 top
PS_TOP  67.31,90.81 180 top
PS_ZEN_FB  84.45,95.25 270 top
Q1  80.01,41.91 0 top
Q1T  80.01,41.91 0 top
Q2  21.59,101.6 0 top
Q2S  100.33,57.78 0 top
Q2T  100.33,55.88 0 top
Q3  119.38,57.15 0 top
Q4  269.88,45.72 0 top
Q5  271.78,64.14 0 top
Q6  85.09,86.36 270 top
Q7  233.68,57.15 0 top
Q8  195.58,57.15 0 top
Q9  156.84,57.78 0 top
Q10  92.71,86.36 270 top
Q10S  80.01,48.26 0 top
Q11  111.12,79.38 0 top
Q12  42.55,38.73 270 top
Q13  42.55,47.62 270 top
Q14  84.45,21.59 270 top
Q15  119.38,55.88 0 top
Q16  160.02,54.61 0 top
Q17  195.58,55.88 0 top
Q18  233.68,55.88 0 top
Q20  140.34,58.42 0 top
Q22  140.34,55.88 0 top
Q23  252.73,57.15 0 top
Q24  214.63,57.15 0 top
Q25  176.53,57.78 0 top
Q26  176.53,55.88 0 top
Q27  214.63,55.88 0 top
Q28  252.73,54.61 0 top
R1  42.04,89.92 90 top
R2  80.01,50.16 270 top
R3  92.71,34.29 90 top
R4  111.76,34.29 270 top
R5  130.81,34.29 270 top
R6  271.78,76.2 270 top
R7  271.78,52.7 180 top
R8  267.97,53.98 270 top
R9  272.42,49.53 0 top
R10  272.42,55.88 180 top
R11  272.42,33.66 180 top
R12  272.42,36.83 0 top
R13  168.91,34.29 270 top
R14  149.86,34.29 270 top
R16  189.23,34.29 270 top
R18  245.11,34.29 270 top
R19  147.96,81.28 270 top
R21  207.01,34.29 270 top
R22  11.43,15.24 270 top
R24  227.33,34.29 270 top
S1  186.06,97.79 0 top
SP1  167,91.08 90 top
T1  273.05,41.27 0 top
TO92S  24.13,60.96 0 top
TRIM0  257.18,15.24 180 top
TRIM0-9  258.44,24.13 0 top
TRIM1  241.3,17.78 180 top
TRIM1-9  241.3,13.97 0 top
TRIM2  219.71,26.67 0 top
TRIM2-7  182.88,12.7 0 top
TRIM2-9  219.07,12.7 0 top
TRIM3  198.75,18.41 180 top
TRIM3-9  204.47,13.97 0 top
TRIM4  182.25,17.78 180 top
TRIM5  165.1,17.78 180 top
TRIM5X  165.1,13.97 0 top
TRIM7  142.24,20.32 180 top
TRIM7X  not placed on the board
TRIM8  121.28,15.24 180 top
TRIM8X  121.28,16.51 0 top
TRIM9  100.33,16.51 180 top
TRIM9X  100.33,17.78 0 top
TRIM10X  79.38,13.34 180 top
U$1  111.12,85.72 0 top
U$2  151.76,90.81 180 top
V-1083  43.18,66.36 270 top
V-TO1  25.04,36.83 225 bottom
V-TO3  25.13,77.11 225 bottom
V-TS  43.18,66.36 270 top
V_C_IN(+)  38.73,47.62 270 top
V_OPTION  19.37,58.55 180 top
VC1  34.29,98.74 0 top
VC2  26.99,95.19 0 top
VC3  19.43,41.15 180 top
VC4  14.61,80.01 180 top
VCBRIDGE1  38.1,50.16 270 top
VENT_RB  98.42,78.74 0 top
VENT_RT  92.71,78.74 0 top
VENTI  114.94,93.98 270 top
VIN(+)  21.59,93.98 270 top
VIN(-)  [1X01']  40.64,96.52 270 top
VIN(-)1  [1X01']  30.48,10.16 270 top
VIN+1  [1X01']  21.59,91.44 270 top
VOUT(+)  6.35,40.64 270 top
VOUT(+)1  237.49,109.86 0 top
VOUT(+)REG  40.64,53.34 270 top
VOUT-  40.64,57.15 180 top
VPOT1  11.43,62.55 270 top
VPOT2  15.24,62.55 270 top
VR1  21.59,69.53 180 top
VR2  32.38,78.42 180 top
VR3  28.26,88.96 270 top
VR4  12.06,73.03 0 top
VR5  21.59,66.04 180 top
VR6  20.32,62.23 90 top
VR7  28.26,88.9 270 top
VR8  32.83,76.83 180 top
VR9  20.32,96.52 0 top
VR10  46.35,83.82 90 top
VR11  84.45,26.04 90 top
VR12  132.72,23.5 90 top
VR13  72.39,13.34 90 top
VR14  72.39,19.68 270 top
VR15  102.23,26.67 0 top
VR16  67.94,95.25 270 top
VR17  132.72,80.01 0 top
VR18  137.79,95.89 0 top
VR19  138.43,80.01 0 top
VR20  not placed on the board
VR21  92.08,22.86 180 top
VR22  77.47,90.81 0 top
VR23  80.64,95.25 90 top
VR24  144.78,33.66 90 top
VR25  167,25.4 0 top
VR26  206.38,24.77 0 top
VR27  243.21,24.77 0 top
VR28  111.12,23.5 0 top
VR29  120.65,27.94 90 top
VR30  158.75,27.94 90 top
VR31  197.49,27.94 90 top
VR32  235.59,27.3 90 top
VR33  190.5,20.95 0 top
VR34  228.6,20.95 0 top
VR35  152.4,20.95 0 top
VR36  139.06,38.73 0 top
VR37  104.78,31.11 90 top
VR38  182.25,26.67 90 top
VR39  not placed on the board
VR40  not placed on the board
VR41  not placed on the board
VR42  not placed on the board
VR43  not placed on the board
VR44  not placed on the board
VR45  not placed on the board
VR46  not placed on the board
VR47  81.92,15.88 180 top
VR48  78.74,15.88 180 top
VR49  83.19,17.78 180 top
VTRIM1  26.35,74.3 90 top
VTRIM2  24.13,15.24 90 top

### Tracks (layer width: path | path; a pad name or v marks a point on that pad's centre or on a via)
ADJ2  (via drill 0.6, 1)  (1 unrouted)
  Top 0.406: TO92S.1 22.23,62.23 C-SO1.4 22.23,63.65 VR6.2 v18.41,63.5 VPOT2.S VPOT1.S | 31.55,74.3 33.02,74.93 | V-1083.1 36.17,74.24 35.56,82.23 C-MABDT1.1 | V-TO3.2 19.68,74.3
  Top 1.27: v40.64,74.61 39.37,73.03 | 19.68,74.3 31.55,74.3 | v22.37,76.39 V-TO3.2
  Bottom 0.406: 39.91,72.3 V-1083.1 40.64,71.56 V-TS.1 | 39.91,72.3 39.37,72.83 | 39.91,72.3 40.64,73.03 v40.64,74.61 41.27,74.93 | v18.41,63.5 19.05,64.14
  Bottom 1.27: 19.05,64.14 arc30 22.23,73.66 v22.37,76.39
  pour Bottom (isolate 0.813, hatched): 39.37,76.83 43.18,76.83 43.18,69.22 41.91,67.94 39.37,67.94
  pour Top (isolate 0.813, hatched): 43.18,80.64 43.18,69.22 41.91,67.94 40.64,67.94 39.37,69.22 34.92,73.03 29.21,74.3 34.29,76.2 34.29,78.11 33.34,85.72
ADJUST  (via drill 0.6)  (3 unrouted)
  Top 0.406: 27.53,37.21 CR2.1 | V-TO1.2 19.22,34.29 v17.02,34.29 17.14,33.66 | 29.21,36.83 C-SO8.4 | 29.21,36.83 29.21,36.2 IC2.1 | 9.62,31.68 8.98,31.68 C.A | D4.1 11.12,25.08 10.16,25.4 8.89,29.21 C.A | A.A C..A C.A | 29.21,36.83 28.57,36.83
  Top 1.016: 27.53,37.21 28.57,37.21 28.57,36.83
  Top 1.27: v29.21,28.26 26.67,28.51 arc-90 17.14,33.66 | CR1.1 16.76,36.01 v17.02,34.29
  Bottom 0.406: C-TS.1 40.64,31.24 C-1083.1 39.5,32.38 | A.A 11.11,31.43 v17.02,34.29 | 29.84,33.02 IC2.1
  Bottom 1.27: 29.84,33.02 29.84,29.84 30.29,29.72 | v29.21,28.26 29.53,28.89 30.29,29.72 | 30.29,29.72 arc-37 37.47,31.75 39.37,31.75 C-1083.1
  Bottom 1.778: Q12.E 38.99,41.02 49.53,40.64
  pour Bottom (isolate 0.813, hatched): 19.68,32.38 arc-90 17.78,30.48 7.62,30.48 arc-90 6.35,31.75 6.35,33.66 arc-90 7.62,34.92 10.79,34.92 arc-90 11.43,35.56 19.68,35.56
  pour Top (isolate 0.61): 29.84,39.37 23.5,39.37 23.5,37.47 28.57,36.2 28.57,35.56 29.84,35.56
B  (4 unrouted)
B1
  Bottom 0.406: 43.18,8.26 43.18,34.92 42.55,35.56 41.53,35.56 Q12.B
  Bottom 0.61: 43.18,8.26 arc-73 19.68,9.53 13.97,8.89 11.43,11.43 CTRIM3.S R22.S
B2  (2 unrouted)
B3  (2 unrouted)
B4  (2 unrouted)
B-Q1
  Top 0.406: C5.2 268.61,44.3 Q4.B 267.33,46.21 267.33,50.8 267.97,51.44 R8.2
BATT-  (via drill 0.6)  (20 unrouted)
  Top 0.406: VR16.2 67,92.88 66.84,92.88 66.04,92.08 66.04,90.94 PS_TOP.2 65.91,88.39 v66.04,88.27 | v84.45,91.44 PS_ZEN_FB.A | Q11.2 v113.67,80.01 113.67,76.2 73.03,76.2 | v102.23,78.74 VENT_RB.2 | v125.73,92.71 DISP_Z.A | C6.A 107.02,91.25 C10.- | v274.64,45.09 274.95,44.45 274.95,41.27 274,40.32 T1.2 274,36.99 R12.2
  Top 0.61: IC1.8 U$2.2
  Bottom 0.406: v66.04,88.27 66.04,78.11 67.31,76.2 84.45,76.2 | 148.59,76.2 249.36,76.2 251.33,76.26 | 148.59,76.2 118.75,76.2 | 118.75,76.2 113.67,76.2 | 113.67,76.2 106.05,76.2 | 106.05,76.2 102.23,76.2 v102.23,78.74 100.33,80.64 90.81,80.64 90.17,80.01 90.17,77.47 88.9,76.2 84.45,76.2 | 84.45,76.2 v84.45,91.44 | 113.67,76.2 v113.67,80.01 | v125.73,92.71 121.28,92.71 118.75,89.53 118.75,76.2 | C10.- 106.05,89.53 106.05,76.2 | 148.59,76.2 v148.59,84.45 149.22,85.09 149.22,94.61 | 149.22,94.61 IC1.8 | C9.- 145.41,93.98 146.05,94.61 149.22,94.61 | 265.43,45.09 v274.64,45.09
  Bottom 2.54: S1.5 197.49,97.79 211.46,83.82 255.27,83.82 | 265.43,45.09 265.43,66.04 255.27,76.2 255.27,83.82 | MINUS60.1 256.62,95.33 255.27,93.34 255.27,83.82
D  (1 unrouted)
GATE
  Top 0.406: Q5.1 269.5,57.37 R10.2 270.99,55.4 271.78,54.61 271.78,51.44 271.14,50.8 271.14,49.68 R9.1 270.51,49.53 269.88,48.9 Q4.C
IN+1
  Top 0.406: 25.1,82.22 V-TO3.1 31.11,81.28 C-MABDT1.3 | TO92S.3 26.04,62.23 26.04,63.5 C-SO1.1
  Top 0.813: 26.04,59.05 26.04,63.5
  pour Bottom (isolate 0.813, hatched): 43.18,64.14 43.18,59.05 36.07,58.93 37.34,64.01
  pour Top (isolate 0.813, rank 3, hatched): 26.67,100.33 26.67,88.27 30.8,85.72 32.7,78.74 21.59,78.74 18.41,76.83 18.41,71.75 26.04,71.75 29.53,66.74 30.99,62.74 arc90 39.37,64.14 43.18,64.14 43.18,59.05 27.3,59.05 26.04,58.42 26.04,64.14 arc90 22.23,67.94 18.1,68.26 15.24,70.17 15.24,80.01 17.14,81.92 19.68,82.55 arc32 23.5,100.33
  pour Bottom (isolate 0.813, rank 4): 29.21,79.38 22.23,79.38 arc-20 23.5,100.33 26.67,100.33 26.67,87 27.94,85.72 31.75,85.72 31.75,80.64
IN-  (via drill 1.3)
  Top 2.54: v203.84,111.12 v40.64,111.12
  Bottom 0.406: 45.72,92.71 VR10.2 43.18,95.89 VIN(-).1
  Bottom 2.54: MINUS120.1 217.88,97.08 v203.84,111.12 | v40.64,111.12 VIN(-).1
  pour Bottom (isolate 0.813, rank 2): 43.18,99.69 47.62,90.81 35.56,90.81 35.56,99.69
  pour Top (isolate 0.813, hatched): 43.18,100.33 43.18,87.63 38.1,87.63 38.1,92.71 35.56,94.61 35.56,100.33
INPUT+  (via drill 0.6, 1)  (1 unrouted)
  Top 0.406: C-SO8.1 32.7,40.96 v30.48,41.91 V-TO1.1 | C-TS.3 40.64,20.83 C-1083.3 | VC3.1 D1.C | 33.02,35.56 IC2.3 | C-SO8.1 33.02,38.73 | C-SO8.1 33.02,38.1 | v30.48,49.78 C-MABDT.3
  Top 0.813: 33.02,38.1 33.02,35.56 33.02,33.66
  Bottom 0.406: C-1083.3 39.5,19.68 38.73,19.68 34.92,20.32 31.75,21.59 29.21,22.86 25.4,24.13 22.86,26.04 22.23,27.94 24.13,32.38 24.77,38.73 24.13,40.64 24.13,41.27 | v30.48,41.91 26.67,43.81 24.13,41.27 | 33.02,41.27 32.38,41.91 v30.48,41.91 | 24.13,41.27 VC3.1 | v30.48,41.91 v30.48,49.78
  pour Top (isolate 0.813, rank 2, hatched): 27.3,53.34 27.3,45.72 26.04,44.45 21.59,44.45 21.59,40.64 22.86,40.64 23.5,40.01 31.75,40.01 31.75,39.37 32.38,38.73 33.02,38.73 32.38,46.35 37.47,45.72 37.47,43.81 43.18,43.81 43.18,48.9 31.75,53.34
  pour Bottom (isolate 0.813, rank 2, hatched): 43.18,50.8 33.02,52.7 27.94,52.7 28.07,46.35 20.95,41.27 20.95,38.73 22.86,36.83 22.86,34.29 19.68,29.84 6.35,29.84 6.35,24.13 arc16 34.92,19.05 40.64,19.68 40.64,23.5 31.11,23.5 25.4,27.3 26.04,37.47 26.67,38.73 33.66,41.27
MINUS
  Top 0.406: D4.2 13.53,20.13 13.51,13.16 13.97,12.7 16.38,12.7 CTRIM3.A
  Bottom 0.406: R22.E 16.43,12.73 CTRIM3.A
MINUS2  (8 unrouted)
MX4  (8 unrouted)
N$1
  Bottom 0.406: VPOT2.A 16.43,60.01 VPOT1.E 17.27,58.55 V_OPTION.2
N$2
  Top 0.406: VR5.2 16.43,66.04 VPOT1.A 13.34,67.94 arc-135 13.34,71.75 VR4.2
  Bottom 0.813: VPOT2.E 17.78,66.47 VPOT1.A
N$3
  Top 0.406: VTRIM1.E VR8.2
  Bottom 0.813: VTRIM1.E 28.89,76.83
  pour Bottom (isolate 0.813, rank 2, hatched): 32.38,78.11 32.38,76.2 32.07,75.56 31.11,75.56 30.48,74.93 27.3,74.93 26.67,75.56 26.67,78.11
N$4
  Bottom 0.406: VR1.1 28.85,69.53 28.85,71.16
  Bottom 0.813: 28.85,71.16 VTRIM1.A
  pour Bottom (isolate 0.813, rank 3, hatched): 31.75,73.66 31.75,73.03 29.21,70.48 27.3,70.48 26.67,71.12 26.67,73.03 27.3,73.66
N$5
  Bottom 0.406: 17.73,18.41 CTRIM3.E 16.43,17.75 R22.A
  Bottom 0.61: VTRIM2.S 21,17.74 19.68,18.41 17.73,18.41
N$6  (1 unrouted)
  Bottom 0.406: 26.52,9.84 VTRIM2.A
N$7
  Top 0.406: VR7.1 VR3.1
  Bottom 0.406: VR3.1 VC1.1 VC2.2
  pour Bottom (isolate 0.813, rank 3): 34.29,90.81 27.3,90.81 27.3,99.69 34.29,99.69
  pour Top (isolate 0.813, rank 4): 34.29,90.81 27.3,90.81 27.3,100.33 34.29,100.33
N$8  (8 unrouted)
N$9  (1 unrouted)
N$10
  Top 0.813: Q2.B 19.05,96.67 VR9.1 D5.C
N$11  (2 unrouted)
N$12  (2 unrouted)
  Top 0.406: VR3.2 VR7.2 29.88,87.83 D7.C
  Bottom 0.406: VR3.2 30.42,85.79 31.75,84.45 VR2.1 33.66,74.55 arc-57 23.56,63.63 20.64,61.78 V_OPTION.1
N$13
  Top 0.406: D6.C 31.75,92.08 D7.A
N$14  (2 unrouted)
N$15  (1 unrouted)
N$16  (1 unrouted)
N$17  (1 unrouted)
N$18
  Top 0.406: T1.3 273.05,46.35 273.69,46.99 273.69,49.38 R9.2
N$19
  Top 0.406: R11.1 273.84,31.9 273.05,31.11 269.24,31.11 268.61,31.75 D16.A
N$20  (2 unrouted)
N$21
  Top 0.406: R11.2 R12.1 270.99,38.58 271.78,39.37 271.78,39.85 T1.1
N$22
  Top 0.406: DISP_V.2 125.09,88.9 125.73,89.53 126.36,89.53 128.91,92.08 128.91,99.06 128.27,99.69 121.96,99.69 121.28,99.01
  Top 0.813: L1.2 97.16,98.42 97.79,99.06 113.67,99.06 | DISP_R.1 122.71,98.91 121.28,99.01 120.65,99.06 113.67,99.06 | 113.67,99.06 VENTI.1
  Bottom 0.406: VENTI.1 C10.+
N$23  (1 unrouted)
N$24  (1 unrouted)
N$25  (4 unrouted)
N$26  (2 unrouted)
N$27  (2 unrouted)
N$29  (1 unrouted)
N$30  (2 unrouted)
N$31  (2 unrouted)
N$32  (1 unrouted)
N$33  (2 unrouted)
N$34  (via drill 0.6)
  Top 0.406: LED3.2 131.42,90.78 128.91,88.27 v128.91,87.63
  Top 0.61: C9.+ 145.41,88.9 148.59,87 IC1.1 U$2.5 | v128.91,87.63 128.91,82.22 DISP_V.3
  Bottom 0.61: C9.+ 130.18,88.27 v128.91,87.63
N$35
  Top 0.61: U$2.1 153.42,91.82 154.31,92.71 IC1.7 154.31,95.25 155.57,99.69 169.54,99.69 170.81,97.79 170.81,78.74 167,74.93 135.89,74.93 134.14,78.59 VR17.2
N$36  (via drill 0.6)
  Top 0.61: v141.6,97.79 141.12,97.79 VR18.2 139.7,95.89 139.7,93.98 142.24,91.44 146.69,91.44 147.07,91.82 U$2.3
  Bottom 0.61: IC1.6 156.84,97.79 v141.6,97.79
N$37
  Top 0.406: 165.74,76.2 156.41,76.2 DISP_Z3.C 156,76.2 140.97,76.2 139.85,77.32 VR19.2
  Top 0.61: IC1.5 161.29,97.16 169.54,97.16 169.54,80.01 165.74,76.2 | U$2.4 147.7,89.79 147.32,90.17 143.51,90.17 140.34,87 140.34,80.49 VR19.2
N$38
  Top 0.813: Q10.3 84.86,84.05 83.82,85.09 83.82,85.24 Q6.E 77.28,85.41 PS_EMIT.2
N$39
  Top 0.406: 89.07,89.11 88.04,89.94 89.53,91.44 | 89.07,89.11 Q10.1 | 89.53,91.44 90.84,91.44 | 90.84,91.44 91.44,91.44 | 90.84,91.44 L2.2 | Q6.B 84.14,87.31 86.36,89.53 88.64,89.53 89.07,89.11 | OK2.3 72.39,96.52 73.66,98.42 86.36,98.42 87,97.16 87,93.34 88.9,91.44 89.53,91.44
N$40
  Top 0.406: Q6.C Q10.2 92.71,86.36 93.34,87 95.25,87 97.16,88.9 L1.1 99.39,90.84 C6.C
N$41
  Top 0.406: OK2.2 80.49,96.52 VR23.2 84.18,96.67 PS_ZEN_FB.C
N$42
  Top 0.406: VR22.2 78.89,91.29 78.74,91.44 78.74,92.08 78.11,92.71 78.11,93.67 OK2.1
N$43  (1 unrouted)
  Top 0.406: 72.39,99.69 88.9,99.69 L2.1 | 68.1,96.52 VR16.1 67.79,96.52 66.04,96.52 64.14,94.61 64.14,85.72 67.31,85.72 68.89,88.58 PS_TOP.1 PS_BOT.2
N$44
  Top 0.813: VENT_RT.2 VENT_RB.1
N$45  (10 unrouted)
  Top 0.406: 71.88,77.15 108.23,77.15 Q11.1
  Top 0.813: U$1.1 108.81,79 Q11.1
N$46
  Top 0.813: DISP_R.2 123.83,95.25 DISP_Z.C 122.12,89.33 121.28,88.27 121.28,82.22 DISP_V.1
N$47
  Top 0.813: VR17.1 131.29,83.15 LED3.1
N$48
  Top 0.61: VR18.1 136.37,91.03 LED3.3
N$49
  Top 0.813: VR19.1 137.01,84.09 LED3.4
N$50  (2 unrouted)
N$51  (2 unrouted)
N$52  (2 unrouted)
N$53
  Top 0.813: VENTI.2 111.12,88.9 U$1.2 Q11.3
N$54  (2 unrouted)
N$55  (2 unrouted)
N$56  (1 unrouted)
N$57  (2 unrouted)
N$58  (3 unrouted)
N$59  (8 unrouted)
N$60  (8 unrouted)
N$61  (3 unrouted)
N$62  (2 unrouted)
N$63  (2 unrouted)
N$64  (2 unrouted)
N$65  (2 unrouted)
N$66  (2 unrouted)
N$67  (2 unrouted)
N$68  (1 unrouted)
N$69  (1 unrouted)
  Top 0.406: DISP_Z1.A 158.96,78.31 157.48,78.11 146.88,78.31
N$70  (1 unrouted)
N$71  (1 unrouted)
N$72  (1 unrouted)
N$73  (1 unrouted)
N$74  (1 unrouted)
N$75  (3 unrouted)
  Top 0.406: U$2.6 156.59,89.79 156.84,89.53 IC1.3
N$76  (1 unrouted)
  Top 0.406: DISP_R1.1 152.41,81.92
N$77  (2 unrouted)
N$78  (2 unrouted)
N$79  (2 unrouted)
N$80  (1 unrouted)
N$81  (1 unrouted)
N$82  (1 unrouted)
N$83
  Top 0.406: DISP_Z1.C 159.38,81.28 161.93,78.74 DISP_Z2.A
N$84  (2 unrouted)
N$85  (4 unrouted)
N$86  (1 unrouted)
N$87  (2 unrouted)
N$88  (2 unrouted)
N$89  (2 unrouted)
N$90  (3 unrouted)
N$91  (1 unrouted)
N$92  (1 unrouted)
N$93  (2 unrouted)
N$94  (2 unrouted)
N$95  (1 unrouted)
N$96  (1 unrouted)
N$97  (3 unrouted)
N$98  (8 unrouted)
N$99  (1 unrouted)
N$100  (2 unrouted)
N$101  (8 unrouted)
N$102  (2 unrouted)
N$103  (2 unrouted)
N$104  (2 unrouted)
N$105  (2 unrouted)
N$106  (2 unrouted)
N$107  (2 unrouted)
N$108  (2 unrouted)
N$109  (2 unrouted)
N$110  (2 unrouted)
N$111  (2 unrouted)
N$112  (2 unrouted)
N$113  (2 unrouted)
N$114  (1 unrouted)
N$115  (1 unrouted)
N$116  (1 unrouted)
N$117  (8 unrouted)
N$118  (1 unrouted)
N$119  (1 unrouted)
N$120  (1 unrouted)
N$121  (2 unrouted)
N$122  (2 unrouted)
N$123  (2 unrouted)
N$124  (1 unrouted)
N$125  (1 unrouted)
N$126  (1 unrouted)
N$128  (2 unrouted)
OUT1
  Top 0.406: 33.02,23.44 V-TO1.3 | C-1083.2 35.83,26.04 V-TO1.3 | IC2.2 31.11,34.29 31.75,33.66 C-SO8.7 31.75,31.11 31.43,30.8 | 26.99,32.7 CR2.2 | 31.43,30.8 31.11,30.48 V-TO1.3 | C-MABDT.4 19.05,49.53 D1.A VC3.2 20.32,39.37 CR1.2 22.92,35.37 23.61,34.48 CR5.2 | 31.11,31.11 31.43,31.11 31.43,30.8
  Top 0.813: 30.48,31.11 31.11,31.11 31.11,38.1
  Bottom 0.406: 13.59,41.4 13.34,43.18 13.34,45.09 | A..C.A 13.59,41.4 | IC2.2 31.11,34.23 31.75,33.28 34.23,33.28 34.92,33.97 34.92,37.47 35.56,38.1 Q12.C | 13.59,41.4 VC3.2
  pour Top: 26.67,46.35 19.68,46.35 arc-90 17.78,44.45 arc-64 10.16,45.09 8.89,46.35 6.35,46.35 6.35,52.7 26.67,52.7
  pour Bottom (isolate 0.813, hatched): 41.91,26.67 40.64,26.67 38.1,29.21 38.1,29.84 37.47,30.48 33.02,30.48 36.2,33.02 36.83,33.66 36.83,36.2 38.73,38.1 39.37,38.1 39.37,38.73 36.83,39.37 34.92,39.37 30.54,39.05 26.42,37.78 26.16,26.1 arc33 36.83,22.23 37.47,22.23
  pour Top (isolate 0.813, rank 3, hatched): 10.79,45.09 19.05,45.09 20.32,43.81 20.32,39.37 17.78,39.37 17.78,36.83 20.95,38.73 22.86,37.47 25.4,34.29 31.11,34.29 38.1,27.3 38.1,20.95 34.92,19.05 32.38,14.61 29.21,14.61 28.57,19.05 21.59,23.5 13.34,26.67 10.79,29.21
  pour Bottom (rank 3): 26.67,46.35 19.68,40.01 15.88,36.2 11.43,36.2 11.43,41.91 9.53,45.72 5.71,45.72 5.71,52.7 26.67,52.7
OUT2  (via drill 0.6)
  Top 0.406: 24.13,59.05 24.07,59.05 C-SO1.7 | 24.13,65.41 23.01,65.41 VR5.1 | v39.37,81.92 C-MABDT1.4 | D3.A F1.1
  Top 0.813: 24.13,59.05 TO92S.2 24.13,65.41
  Bottom 0.406: 40.2,66.41 V-1083.2 V-TS.2 | 37.47,77.47 v39.37,81.92 | V-TO3.3 29.84,60.33 27.3,57.78 24.13,57.78 TO92S.2 | F1.1 8.89,93.34
  Bottom 1.27: 14.67,83.82 13.46,85.66 8.89,93.34 | V-1083.2 V-TO3.3 36.2,70.55 37.02,73.91 37.47,77.47
  other vias: 41.27,81.92 41.27,83.82 39.37,83.82
  pour Bottom (isolate 0.813, rank 6, hatched): 38.73,64.14 36.83,62.87 35.56,62.87 35.56,62.23 arc-68 15.88,54.61 arc-90 9.53,61.59 9.53,74.3 11.43,74.93 11.43,81.92 6.35,81.92 6.35,95.25 15.88,95.25 15.88,77.47 14.61,74.93 14.61,57.15 25.08,60.96 27.94,63.18 31.11,66.67 33.02,69.85 36.2,74.3 arc16 35.56,89.22 43.81,89.22 43.81,77.91 38.73,77.79
  pour Top (isolate 0.254, rank 2, hatched): 17.14,81.92 6.35,81.92 6.35,97.16 14.61,97.16 14.61,94.61 17.14,94.61 17.14,88.9
OUT+
  Top 0.406: A.C C..C C.C
  pour Bottom (isolate 0.813, rank 2, hatched): 10.79,36.2 5.71,36.2 5.71,46.35 8.89,45.72 10.79,43.81
PLUS5  (via drill 0.6, 1.3)  (1 unrouted)
  Top 0.406: OK2.4 72.39,93.98 73.97,92.39 PS_BOT.1 VR22.1 76.05,89.69 | 76.05,89.69 76.83,88.27 81.28,88.27 81.28,92.71 80.64,93.34 VR23.1 | 74.17,86.36 74.17,88.14 v74.3,88.27 76.05,89.69 | 74.17,86.36 PS_EMIT.1 | VENT_RT.1 76.2,78.74 74.3,81.28 74.17,86.36 | DISP_Z2.C 164.26,81.71 v164.47,81.92 | D16.C C5.1 269.11,39.24 270.51,40.64 270.51,43.18 271.14,43.81 271.14,44.3 Q4.E 270.82,44.77 271.78,45.72 271.78,46.99 272.42,47.62 272.42,50.8 273.05,51.44 273.05,52.55 R7.1 273.2,53.49 274.32,54.61 274.32,55.4 R10.1 273.84,59.11 Q5.2
  Top 0.61: 274.32,59.05 274.32,59.08 Q5.2
  Top 1.422: 275.59,59.69 275.59,60.33 274.32,59.05
  Top 2.54: v196.85,79.38 199.39,79.38 202.56,76.2 274.32,76.2 276.86,73.66 276.86,60.96 275.59,59.69
  Bottom 0.406: v74.3,88.27 74.3,102.23 | v164.47,81.92 173.35,81.92 173.99,81.28
  Bottom 2.54: 178.44,97.16 173.99,93.34 173.99,81.28 176.53,79.38 v196.85,79.38
PLUS10  (8 unrouted)
  Bottom 2.54: Q1.E 85.47,31.37 87.63,29.21 87.63,6.35 MINUS10.1
PLUS11  (4 unrouted)
  Top 0.61: VR13.1 71.6,7.47 69.85,5.71 PLUS11.1
  Bottom 2.54: R2.2 73.66,27.3 71.12,24.77 71.12,6.99 69.85,5.71 PLUS11.1 69.22,4.45 60.33,13.34 60.33,97.16 65.41,102.23 175.9,102.23 180.34,97.79 S1.2
Q1C  (1 unrouted)
  pour Top (isolate 0.813, hatched): 87.63,74.3 88.27,29.84 70.48,29.84 69.85,74.3
Q1C1  (3 unrouted)
Q2C  (1 unrouted)
  pour Top (isolate 0.813, hatched): 125.73,72.39 125.73,34.92 107.95,34.92 107.95,72.39
Q2C1  (3 unrouted)
  pour Top (isolate 0.813, rank 2, hatched): 108.58,72.39 108.58,34.92 88.9,34.92 88.9,72.39
Q3C  (3 unrouted)
Q3C1  (3 unrouted)
V+OUT  (via drill 0.6)
  Top 0.406: 267.33,55.88 267.49,55.88 R8.1 267.97,55.24 269.56,54.23 269.88,53.19 R7.2
  Top 0.61: 267.33,55.88 267.33,71.12 v267.97,72.39
  Bottom 0.61: R6.1 271.14,80.01 | v267.97,72.39 267.97,79.38 268.61,80.01 271.93,80.01 272.22,80.3
  Bottom 1.27: 237.49,107.31 VOUT(+)1.1
  Bottom 2.54: R6.1 272.22,80.3 275.59,82.55 275.59,104.14 269.88,109.86 240.03,109.86 237.49,107.31 237.49,98.42 237.62,98.3 PLUS120.1
V-  (1 unrouted)
  Top 1.778: R1.1 45,87.72 46.35,87 VR10.1 46.35,59.05 43.81,56.52 VOUT-.1 36.2,56.52 C1.-
  Bottom 2.54: S1.4 190.98,109.37 189.23,111.12 53.34,111.12 51.44,109.22 51.44,64.14 44.45,57.15 VOUT-.1
VIN+  (via drill 1.3)
  Top 0.406: VR9.2 21.74,94.13 VIN(+).1
  Top 1.778: 21.59,101.6 Q2.C
  Top 2.54: v189.87,83.82 177.16,83.82 173.99,87 173.99,104.14 171.45,106.68 26.67,106.68 21.59,101.6
  Bottom 0.406: VIN+1.1 VIN(+).1 Q2.C
  Bottom 2.54: S1.6 190.98,84.94 v189.87,83.82
VIRT-  (2 unrouted)
  Top 0.406: D2.C 35.67,92.39 D6.A
  Bottom 0.813: C3.- 26.67,87.63 28.57,89.53 31.11,89.53 31.75,90.17 33.18,90.17 C2.-
VOUT+REG
  Top 0.406: VR4.1 F1.2
  Bottom 2.54: S1.1 178.23,105.61 177.16,106.68 60.96,106.68 55.88,101.6 55.88,62.23 46.99,53.34 VOUT(+)REG.1
  pour Top (isolate 0.813, hatched): 43.18,49.53 39.37,49.53 arc25 33.02,53.98 31.11,54.61 12.7,54.61 arc-73 6.35,66.67 6.35,80.64 13.97,80.64 11.43,67.94 13.34,64.77 13.34,57.78 19.05,57.15 34.92,57.15 43.18,52.07

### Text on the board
Top: MICHAELS | 24112011
Bottom: 14042012 | MICHAELS
tNames: V_in(+) | V_out(+)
